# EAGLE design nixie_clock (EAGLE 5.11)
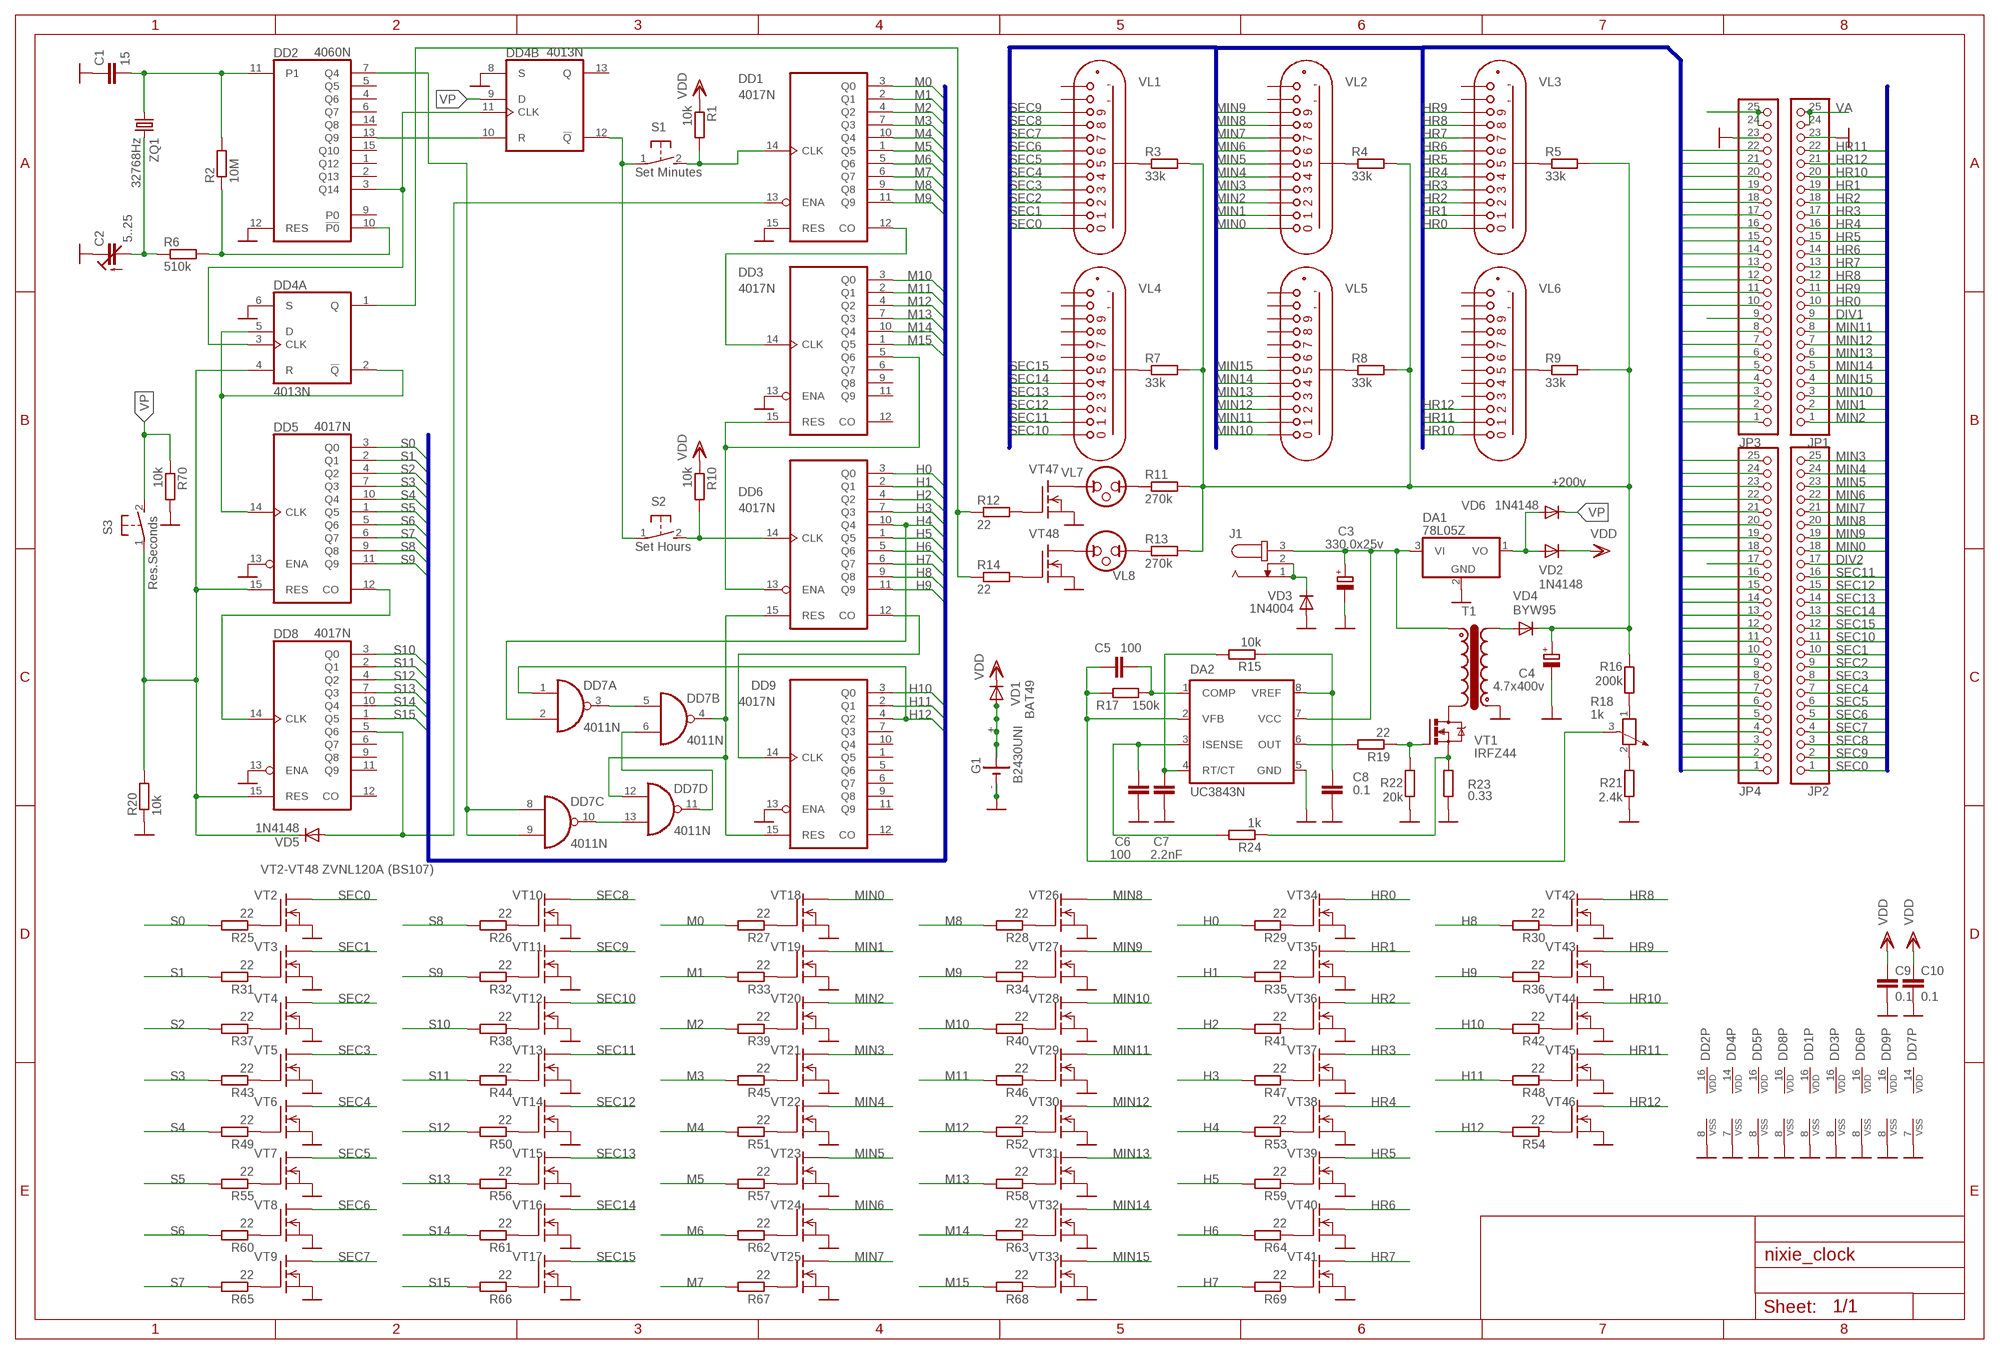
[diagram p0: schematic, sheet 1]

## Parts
C1  15  C-EU050-025X075  [C050-025X075]
C2  5..25  C-TRIMM3040.452  [CTRIM3040.452]
C3  330.0x25v  CPOL-EUE3.5-8  [E3,5-8]
C4  4.7x400v  CPOL-EUE5-10.5  [E5-10,5]
C5  100  C-EU050-025X075  [C050-025X075]
C6  100  C-EU050-025X075  [C050-025X075]
C7  2.2nF  C-EU050-025X075  [C050-025X075]
C8  0.1  C-EU050-025X075  [C050-025X075]
C9  0.1  C-EU050-025X075  [C050-025X075]
C10  0.1  C-EU050-025X075  [C050-025X075]
DA1  78L05Z  78L12Z  [TO92]
DA2  UC3843N  UC3842N  [DIL08]
DD1  4017N  [DIL16]
DD2  4060N  [DIL16]
DD3  4017N  [DIL16]
DD4  4013N  [DIL14]
DD5  4017N  [DIL16]
DD6  4017N  [DIL16]
DD7  4011N  [DIL14]
DD8  4017N  [DIL16]
DD9  4017N  [DIL16]
G1  B2430UNI  [B2430UNI]
J1  JACK-PLUG1  [SPC4078]
JP1  PINHD-1X25  [1X25]
JP2  PINHD-1X25  [1X25]
JP3  PINHD-1X25  [1X25]
JP4  PINHD-1X25  [1X25]
R1  10k  R-EU_0207/12  [0207/12]
R2  10M  R-EU_0207/10  [0207/10]
R3  33k  R-EU_0207/12  [0207/12]
R4  33k  R-EU_0207/12  [0207/12]
R5  33k  R-EU_0207/12  [0207/12]
R6  510k  R-EU_0207/10  [0207/10]
R7  33k  R-EU_0207/12  [0207/12]
R8  33k  R-EU_0207/12  [0207/12]
R9  33k  R-EU_0207/12  [0207/12]
R10  10k  R-EU_0207/12  [0207/12]
R11  270k  R-EU_0207/12  [0207/12]
R12  22  R-EU_0207/10  [0207/10]
R13  270k  R-EU_0207/12  [0207/12]
R14  22  R-EU_0207/2V  [0207/2V]
R15  10k  R-EU_0207/10  [0207/10]
R16  200k  R-EU_0207/10  [0207/10]
R17  150k  R-EU_0207/12  [0207/12]
R18  1k  POTENTIOMETER_PT-10  [PT-10]
R19  22  R-EU_0207/10  [0207/10]
R20  10k  R-EU_0207/12  [0207/12]
R21  2.4k  R-EU_0207/12  [0207/12]
R22  20k  R-EU_0207/12  [0207/12]
R23  0.33  R-EU_0207/10  [0207/10]
R24  1k  R-EU_0207/10  [0207/10]
R25  22  R-EU_0207/2V  [0207/2V]
R26  22  R-EU_0207/2V  [0207/2V]
R27  22  R-EU_0207/10  [0207/10]
R28  22  R-EU_0207/10  [0207/10]
R29  22  R-EU_0207/2V  [0207/2V]
R30  22  R-EU_0207/2V  [0207/2V]
R31  22  R-EU_0207/10  [0207/10]
R32  22  R-EU_0207/10  [0207/10]
R33  22  R-EU_0207/2V  [0207/2V]
R34  22  R-EU_0207/2V  [0207/2V]
R35  22  R-EU_0207/10  [0207/10]
R36  22  R-EU_0207/10  [0207/10]
R37  22  R-EU_0207/2V  [0207/2V]
R38  22  R-EU_0207/2V  [0207/2V]
R39  22  R-EU_0207/10  [0207/10]
R40  22  R-EU_0207/10  [0207/10]
R41  22  R-EU_0207/2V  [0207/2V]
R42  22  R-EU_0207/2V  [0207/2V]
R43  22  R-EU_0207/10  [0207/10]
R44  22  R-EU_0207/10  [0207/10]
R45  22  R-EU_0207/2V  [0207/2V]
R46  22  R-EU_0207/2V  [0207/2V]
R47  22  R-EU_0207/10  [0207/10]
R48  22  R-EU_0207/2V  [0207/2V]
R49  22  R-EU_0207/2V  [0207/2V]
R50  22  R-EU_0207/2V  [0207/2V]
R51  22  R-EU_0207/10  [0207/10]
R52  22  R-EU_0207/10  [0207/10]
R53  22  R-EU_0207/2V  [0207/2V]
R54  22  R-EU_0207/10  [0207/10]
R55  22  R-EU_0207/10  [0207/10]
R56  22  R-EU_0207/10  [0207/10]
R57  22  R-EU_0207/2V  [0207/2V]
R58  22  R-EU_0207/2V  [0207/2V]
R59  22  R-EU_0207/10  [0207/10]
R60  22  R-EU_0207/2V  [0207/2V]
R61  22  R-EU_0207/2V  [0207/2V]
R62  22  R-EU_0207/10  [0207/10]
R63  22  R-EU_0207/10  [0207/10]
R64  22  R-EU_0207/2V  [0207/2V]
R65  22  R-EU_0207/10  [0207/10]
R66  22  R-EU_0207/10  [0207/10]
R67  22  R-EU_0207/2V  [0207/2V]
R68  22  R-EU_0207/2V  [0207/2V]
R69  22  R-EU_0207/10  [0207/10]
R70  10k  R-EU_0207/12  [0207/12]
S1  31-XX  [B3F-31XX]
S2  31-XX  [B3F-31XX]
S3  31-XX  [B3F-31XX]
U$1  TRANSFFB  [EFD20-8]
VD1  BAT49  1N4148DO35-10  [DO35-10]
VD2  1N4148  1N4148DO35-10  [DO35-10]
VD3  1N4004  [DO41-10]
VD4  BYW95  [SOD64-10]
VD5  1N4148  1N4148DO35-10  [DO35-10]
VD6  1N4148  1N4148DO35-10  [DO35-10]
VL1  IN14  [IN14]
VL2  IN14  [IN14]
VL3  IN14  [IN14]
VL4  IN14  [IN14]
VL5  IN14  [IN14]
VL6  IN14  [IN14]
VL7  NE2SMALL  [NE2SMALL]
VL8  NE2SMALL  [NE2SMALL]
VT1  IRFZ44  IRF740  [TO220BV]
VT2  VN2222KM  [TO237]
VT3  VN2222KM  [TO237]
VT4  VN2222KM  [TO237]
VT5  VN2222KM  [TO237]
VT6  VN2222KM  [TO237]
VT7  VN2222KM  [TO237]
VT8  VN2222KM  [TO237]
VT9  VN2222KM  [TO237]
VT10  VN2222KM  [TO237]
VT11  VN2222KM  [TO237]
VT12  VN2222KM  [TO237]
VT13  VN2222KM  [TO237]
VT14  VN2222KM  [TO237]
VT15  VN2222KM  [TO237]
VT16  VN2222KM  [TO237]
VT17  VN2222KM  [TO237]
VT18  VN2222KM  [TO237]
VT19  VN2222KM  [TO237]
VT20  VN2222KM  [TO237]
VT21  VN2222KM  [TO237]
VT22  VN2222KM  [TO237]
VT23  VN2222KM  [TO237]
VT24  VN2222KM  [TO237]
VT25  VN2222KM  [TO237]
VT26  VN2222KM  [TO237]
VT27  VN2222KM  [TO237]
VT28  VN2222KM  [TO237]
VT29  VN2222KM  [TO237]
VT30  VN2222KM  [TO237]
VT31  VN2222KM  [TO237]
VT32  VN2222KM  [TO237]
VT33  VN2222KM  [TO237]
VT34  VN2222KM  [TO237]
VT35  VN2222KM  [TO237]
VT36  VN2222KM  [TO237]
VT37  VN2222KM  [TO237]
VT38  VN2222KM  [TO237]
VT39  VN2222KM  [TO237]
VT40  VN2222KM  [TO237]
VT41  VN2222KM  [TO237]
VT42  VN2222KM  [TO237]
VT43  VN2222KM  [TO237]
VT44  VN2222KM  [TO237]
VT45  VN2222KM  [TO237]
VT46  VN2222KM  [TO237]
VT47  VN2222KM  [TO237]
VT48  VN2222KM  [TO237]
ZQ1  32768Hz  CRYSTALTC38H  [TC38H]

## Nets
DIV: DD4.1(A:Q) R12.1 R14.1
DIV1: JP1.9 JP3.9 VL7.P$1 VT47.1(D)
DIV2: JP2.17 JP4.17 VL8.P$1 VT48.1(D)
GND: C1.1 C2.1A(E) C3.- C4.- C6.1 C7.1 C8.1 C9.1 C10.1 DA1.2(GND) DA2.5(GND) DD1.8(VSS) DD1.15(RES) DD2.8(VSS) DD2.12(RES) DD3.8(VSS) DD3.13(ENA) DD4.6(A:S) DD4.7(P:VSS) DD4.8(B:S) DD5.8(VSS) DD5.13(ENA) DD6.8(VSS) DD7.7(P:VSS) DD8.8(VSS) DD8.13(ENA) DD9.8(VSS) DD9.13(ENA) G1.- G1.-@1(-) JP1.23 JP3.23 R20.1 R21.1 R22.1 R23.1 R70.2 U$1.P$1 VD3.A VT2.3(S) VT3.3(S) VT4.3(S) VT5.3(S) VT6.3(S) VT7.3(S) VT8.3(S) VT9.3(S) VT10.3(S) VT11.3(S) VT12.3(S) VT13.3(S) VT14.3(S) VT15.3(S) VT16.3(S) VT17.3(S) VT18.3(S) VT19.3(S) VT20.3(S) VT21.3(S) VT22.3(S) VT23.3(S) VT24.3(S) VT25.3(S) VT26.3(S) VT27.3(S) VT28.3(S) VT29.3(S) VT30.3(S) VT31.3(S) VT32.3(S) VT33.3(S) VT34.3(S) VT35.3(S) VT36.3(S) VT37.3(S) VT38.3(S) VT39.3(S) VT40.3(S) VT41.3(S) VT42.3(S) VT43.3(S) VT44.3(S) VT45.3(S) VT46.3(S) VT47.3(S) VT48.3(S)
H0: DD6.3(Q0) R29.2
H1: DD6.2(Q1) R35.2
H2: DD6.4(Q2) R41.2
H3: DD6.7(Q3) R47.2
H4: DD6.10(Q4) DD7.2(A:I1) R53.2
H5: DD6.1(Q5) R59.2
H6: DD6.5(Q6) R64.2
H7: DD6.6(Q7) R69.2
H8: DD6.9(Q8) R30.2
H9: DD6.11(Q9) R36.2
H10: DD9.3(Q0) R42.2
H11: DD9.2(Q1) R48.2
H12: DD7.1(A:I0) DD9.4(Q2) R54.2
HR0: JP1.10 JP3.10 VL3.P12 VT34.1(D)
HR1: JP1.19 JP3.19 VL3.P3 VT35.1(D)
HR2: JP1.18 JP3.18 VL3.P4 VT36.1(D)
HR3: JP1.17 JP3.17 VL3.P5 VT37.1(D)
HR4: JP1.16 JP3.16 VL3.P6 VT38.1(D)
HR5: JP1.15 JP3.15 VL3.P7 VT39.1(D)
HR6: JP1.14 JP3.14 VL3.P8 VT40.1(D)
HR7: JP1.13 JP3.13 VL3.P9 VT41.1(D)
HR8: JP1.12 JP3.12 VL3.P10 VT42.1(D)
HR9: JP1.11 JP3.11 VL3.P11 VT43.1(D)
HR10: JP1.20 JP3.20 VL6.P12 VT44.1(D)
HR11: JP1.22 JP3.22 VL6.P3 VT45.1(D)
HR12: JP1.21 JP3.21 VL6.P4 VT46.1(D)
M0: DD1.3(Q0) R27.2
M1: DD1.2(Q1) R33.2
M2: DD1.4(Q2) R39.2
M3: DD1.7(Q3) R45.2
M4: DD1.10(Q4) R51.2
M5: DD1.1(Q5) R57.2
M6: DD1.5(Q6) R62.2
M7: DD1.6(Q7) R67.2
M8: DD1.9(Q8) R28.2
M9: DD1.11(Q9) R34.2
M10: DD3.3(Q0) R40.2
M11: DD3.2(Q1) R46.2
M12: DD3.4(Q2) R52.2
M13: DD3.7(Q3) R58.2
M14: DD3.10(Q4) R63.2
M15: DD3.1(Q5) R68.2
MIN0: JP2.18 JP4.18 VL2.P12 VT18.1(D)
MIN1: JP1.2 JP3.2 VL2.P3 VT19.1(D)
MIN2: JP1.1 JP3.1 VL2.P4 VT20.1(D)
MIN3: JP2.25 JP4.25 VL2.P5 VT21.1(D)
MIN4: JP2.24 JP4.24 VL2.P6 VT22.1(D)
MIN5: JP2.23 JP4.23 VL2.P7 VT23.1(D)
MIN6: JP2.22 JP4.22 VL2.P8 VT24.1(D)
MIN7: JP2.21 JP4.21 VL2.P9 VT25.1(D)
MIN8: JP2.20 JP4.20 VL2.P10 VT26.1(D)
MIN9: JP2.19 JP4.19 VL2.P11 VT27.1(D)
MIN10: JP1.3 JP3.3 VL5.P12 VT28.1(D)
MIN11: JP1.8 JP3.8 VL5.P3 VT29.1(D)
MIN12: JP1.7 JP3.7 VL5.P4 VT30.1(D)
MIN13: JP1.6 JP3.6 VL5.P5 VT31.1(D)
MIN14: JP1.5 JP3.5 VL5.P6 VT32.1(D)
MIN15: JP1.4 JP3.4 VL5.P7 VT33.1(D)
N$1: DD1.12(CO) DD3.14(CLK)
N$2: DD3.5(Q6) DD3.15(RES) DD6.13(ENA)
N$3: DD4.12(B:!Q) S1.1(P) S2.1(P)
N$4: DD6.12(CO) DD9.14(CLK)
N$5: DD6.15(RES) DD7.4(B:O) DD7.12(D:I0) DD9.15(RES)
N$6: R11.1 VL7.P$2
N$7: DD1.14(CLK) R1.2 S1.2(S)
N$8: DD4.2(A:!Q) DD4.5(A:D) DD5.14(CLK)
N$9: DD2.3(Q14) DD4.3(A:CLK) DD4.11(B:CLK)
N$10: DD2.13(Q9) DD4.10(B:R)
N$11: DD1.13(ENA) DD8.5(Q6) VD5.A
N$12: DD5.12(CO) DD8.14(CLK)
N$13: DD7.6(B:I1) DD7.11(D:O)
N$14: DD4.4(A:R) DD5.15(RES) DD8.15(RES) R20.2 S3.1(P) VD5.C
N$15: R27.1 VT18.2(G)
N$16: R33.1 VT19.2(G)
N$17: R39.1 VT20.2(G)
N$18: R45.1 VT21.2(G)
N$19: R51.1 VT22.2(G)
N$20: R57.1 VT23.2(G)
N$21: R62.1 VT24.2(G)
N$22: R67.1 VT25.2(G)
N$23: R68.1 VT33.2(G)
N$24: R63.1 VT32.2(G)
N$25: R58.1 VT31.2(G)
N$26: R52.1 VT30.2(G)
N$27: R46.1 VT29.2(G)
N$28: R40.1 VT28.2(G)
N$29: R34.1 VT27.2(G)
N$30: R28.1 VT26.2(G)
N$31: R29.1 VT34.2(G)
N$32: R35.1 VT35.2(G)
N$33: R41.1 VT36.2(G)
N$34: R47.1 VT37.2(G)
N$35: R53.1 VT38.2(G)
N$36: R59.1 VT39.2(G)
N$37: R64.1 VT40.2(G)
N$38: R69.1 VT41.2(G)
N$39: R54.1 VT46.2(G)
N$40: R48.1 VT45.2(G)
N$41: R42.1 VT44.2(G)
N$42: R36.1 VT43.2(G)
N$43: R30.1 VT42.2(G)
N$44: R25.1 VT2.2(G)
N$45: R31.1 VT3.2(G)
N$46: R37.1 VT4.2(G)
N$47: R43.1 VT5.2(G)
N$48: DA1.1(VO) VD2.A VD6.A
N$49: R19.1 R22.2 VT1.G
N$50: U$1.P$5 VD4.A
N$51: DA2.6(OUT) R19.2
N$52: R23.2 R24.1 VT1.S
N$53: DD6.14(CLK) R10.2 S2.2(S)
N$54: R49.1 VT6.2(G)
N$55: R55.1 VT7.2(G)
N$56: R60.1 VT8.2(G)
N$57: U$1.P$7 VT1.D
N$58: C5.2 DA2.2(VFB) R17.2 R18.3
N$59: R4.1 VL2.P1(ANODE)
N$61: J1.1 J1.2 VD3.C
N$62: R8.1 VL5.P1(ANODE)
N$63: R5.1 VL3.P1(ANODE)
N$64: R9.1 VL6.P1(ANODE)
N$65: R65.1 VT9.2(G)
N$66: R66.1 VT17.2(G)
N$67: R12.2 VT47.2(G)
N$69: R61.1 VT16.2(G)
N$70: R56.1 VT15.2(G)
N$71: R50.1 VT14.2(G)
N$72: R44.1 VT13.2(G)
N$73: R38.1 VT12.2(G)
N$74: R32.1 VT11.2(G)
N$75: R26.1 VT10.2(G)
N$76: R3.1 VL1.P1(ANODE)
N$77: R7.1 VL4.P1(ANODE)
N$78: R14.2 VT48.2(G)
N$80: R13.1 VL8.P$2
N$81: DD7.3(A:O) DD7.5(B:I0)
N$82: R18.2 R21.2
N$83: C8.2 DA2.8(VREF) R15.1
N$84: C7.2 DA2.4(RT/CT) R15.2
N$85: C6.2 DA2.3(ISENSE) R24.2
N$86: R16.1 R18.1
N$87: DD2.10(!P0) R2.1 R6.2
N$88: C1.2 DD2.11(P1) R2.2 ZQ1.1
N$89: C2.2(A) R6.1 ZQ1.2
N$90: C5.1 DA2.1(COMP) R17.1
N$91: DD7.10(C:O) DD7.13(D:I1)
N$92: DD2.7(Q4) DD7.8(C:I0) DD7.9(C:I1)
N$93: G1.+ G1.+@1(+) G1.+@2(+) G1.+@3(+) G1.+@4(+) VD1.A
S0: DD5.3(Q0) R25.2
S1: DD5.2(Q1) R31.2
S2: DD5.4(Q2) R37.2
S3: DD5.7(Q3) R43.2
S4: DD5.10(Q4) R49.2
S5: DD5.1(Q5) R55.2
S6: DD5.5(Q6) R60.2
S7: DD5.6(Q7) R65.2
S8: DD5.9(Q8) R26.2
S9: DD5.11(Q9) R32.2
S10: DD8.3(Q0) R38.2
S11: DD8.2(Q1) R44.2
S12: DD8.4(Q2) R50.2
S13: DD8.7(Q3) R56.2
S14: DD8.10(Q4) R61.2
S15: DD8.1(Q5) R66.2
SEC0: JP2.1 JP4.1 VL1.P12 VT2.1(D)
SEC1: JP2.10 JP4.10 VL1.P3 VT3.1(D)
SEC2: JP2.9 JP4.9 VL1.P4 VT4.1(D)
SEC3: JP2.8 JP4.8 VL1.P5 VT5.1(D)
SEC4: JP2.7 JP4.7 VL1.P6 VT6.1(D)
SEC5: JP2.6 JP4.6 VL1.P7 VT7.1(D)
SEC6: JP2.5 JP4.5 VL1.P8 VT8.1(D)
SEC7: JP2.4 JP4.4 VL1.P9 VT9.1(D)
SEC8: JP2.3 JP4.3 VL1.P10 VT10.1(D)
SEC9: JP2.2 JP4.2 VL1.P11 VT11.1(D)
SEC10: JP2.11 JP4.11 VL4.P12 VT12.1(D)
SEC11: JP2.16 JP4.16 VL4.P3 VT13.1(D)
SEC12: JP2.15 JP4.15 VL4.P4 VT14.1(D)
SEC13: JP2.14 JP4.14 VL4.P5 VT15.1(D)
SEC14: JP2.13 JP4.13 VL4.P6 VT16.1(D)
SEC15: JP2.12 JP4.12 VL4.P7 VT17.1(D)
T1: C3.+ DA1.3(VI) DA2.7(VCC) J1.3 U$1.P$3
VA: C4.+ JP1.24 JP1.25 JP3.24 JP3.25 R3.2 R4.2 R5.2 R7.2 R8.2 R9.2 R11.2 R13.2 R16.2 VD4.C
VDD: C9.2 C10.2 R1.1 R10.1 VD1.C VD2.C
VP: DD4.9(B:D) R70.1 S3.2(S) VD6.C
Unconnected: DD2.1(Q12) DD2.2(Q13) DD2.4(Q6) DD2.5(Q5) DD2.6(Q7) DD2.9(P0) DD2.14(Q8) DD2.15(Q10) DD3.6(Q7) DD3.9(Q8) DD3.11(Q9) DD3.12(CO) DD4.13(B:Q) DD8.6(Q7) DD8.9(Q8) DD8.11(Q9) DD8.12(CO) DD9.1(Q5) DD9.5(Q6) DD9.6(Q7) DD9.7(Q3) DD9.9(Q8) DD9.10(Q4) DD9.11(Q9) DD9.12(CO) VL1.P2(CL) VL1.P13(CR) VL2.P2(CL) VL2.P13(CR) VL3.P2(CL) VL3.P13(CR) VL4.P2(CL) VL4.P8 VL4.P9 VL4.P10 VL4.P11 VL4.P13(CR) VL5.P2(CL) VL5.P8 VL5.P9 VL5.P10 VL5.P11 VL5.P13(CR) VL6.P2(CL) VL6.P5 VL6.P6 VL6.P7 VL6.P8 VL6.P9 VL6.P10 VL6.P11 VL6.P13(CR)

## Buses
S[0..15],M[0..15],H[0..12],DIV
SEC[0..15],MIN[0..15],HR[0..12]

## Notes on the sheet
- VL1 | VL2 | VL3
- Set Minutes
- VL4 | VL5 | VL6
- +200v
- Set Hours
- Res.Seconds
- T1
- VT2-VT48 ZVNL120A (BS107)

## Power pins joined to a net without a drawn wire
VDD: DD1.16(VDD) DD2.16(VDD) DD3.16(VDD) DD4.14(P:VDD) DD5.16(VDD) DD6.16(VDD) DD7.14(P:VDD) DD8.16(VDD) DD9.16(VDD)

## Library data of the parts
C1 C5-C10 = rcl:C-EU: CAPACITOR, European symbol
C2 = rcl:C-TRIMM: Trimm capacitor
C3 C4 = rcl:CPOL-EU: POLARIZED CAPACITOR, European symbol
DA1 = linear:78*: Positive VOLTAGE REGULATOR Source: http://cache.national.com/ds/LM/LM78L05.pdf http://www.fairchildsemi.com/ds/LM/LM7805.pdf
DA2 = v-reg:UC384*: SMPS Controller Source: http://www.fairchildsemi.com/ds/UC/UC3843.pdf
DD1 DD3 DD5 DD6 DD8 DD9 = 40xx:4017: COUNTER/DIVIDER
DD2 = 40xx:4060: 14-stage binary/ripple COUNTER
DD4 = 40xx:4013: Dual D FLIP FLOP, set/reset
DD7 = 40xx:4011: Quad 2-input NAND
G1 = battery:B2430UNI: LI BATTERY
J1 = con-jack:JACK-PLUG: DC POWER JACK Power Jack, DC, Right Angle, Through Hole, Rated 5A at 16VDC, PC Terminals Distributor: Farnell (www.Farnell.de) Drawing: 84N1161.pdf / 84N1162.pdf Manufacturer: SPC Technology (www.spctechnology.com) Type: SPC4077 / SPC 4078
JP1-JP4 = pinhead:PINHD-1X25: PIN HEADER
R1-R17 R19-R70 = rcl:R-EU_: RESISTOR, European symbol
R18 = rcl:POTENTIOMETER_: Potentiometer
S1-S3 = switch-omron:31-XX: OMRON SWITCH
U$1 = rps45:TRANSFFB
VD1 VD2 VD5 VD6 = diode:1N4148: DIODE
VD3 = diode:1N4004: DIODE
VD4 = diode:BYW95: DIODE
VL1-VL6 = rps45:IN14
VL7 VL8 = rps45:NE2
VT1 = transistor-power:IRF740: N-CHANNEL MOS FET
VT2-VT48 = transistor-fet:VN2222KM: N-Channel Enhancement MOSFET (VMOS); 60V; 0,5A; 7,5Ohm
ZQ1 = crystal:CRYSTAL: CRYSTAL

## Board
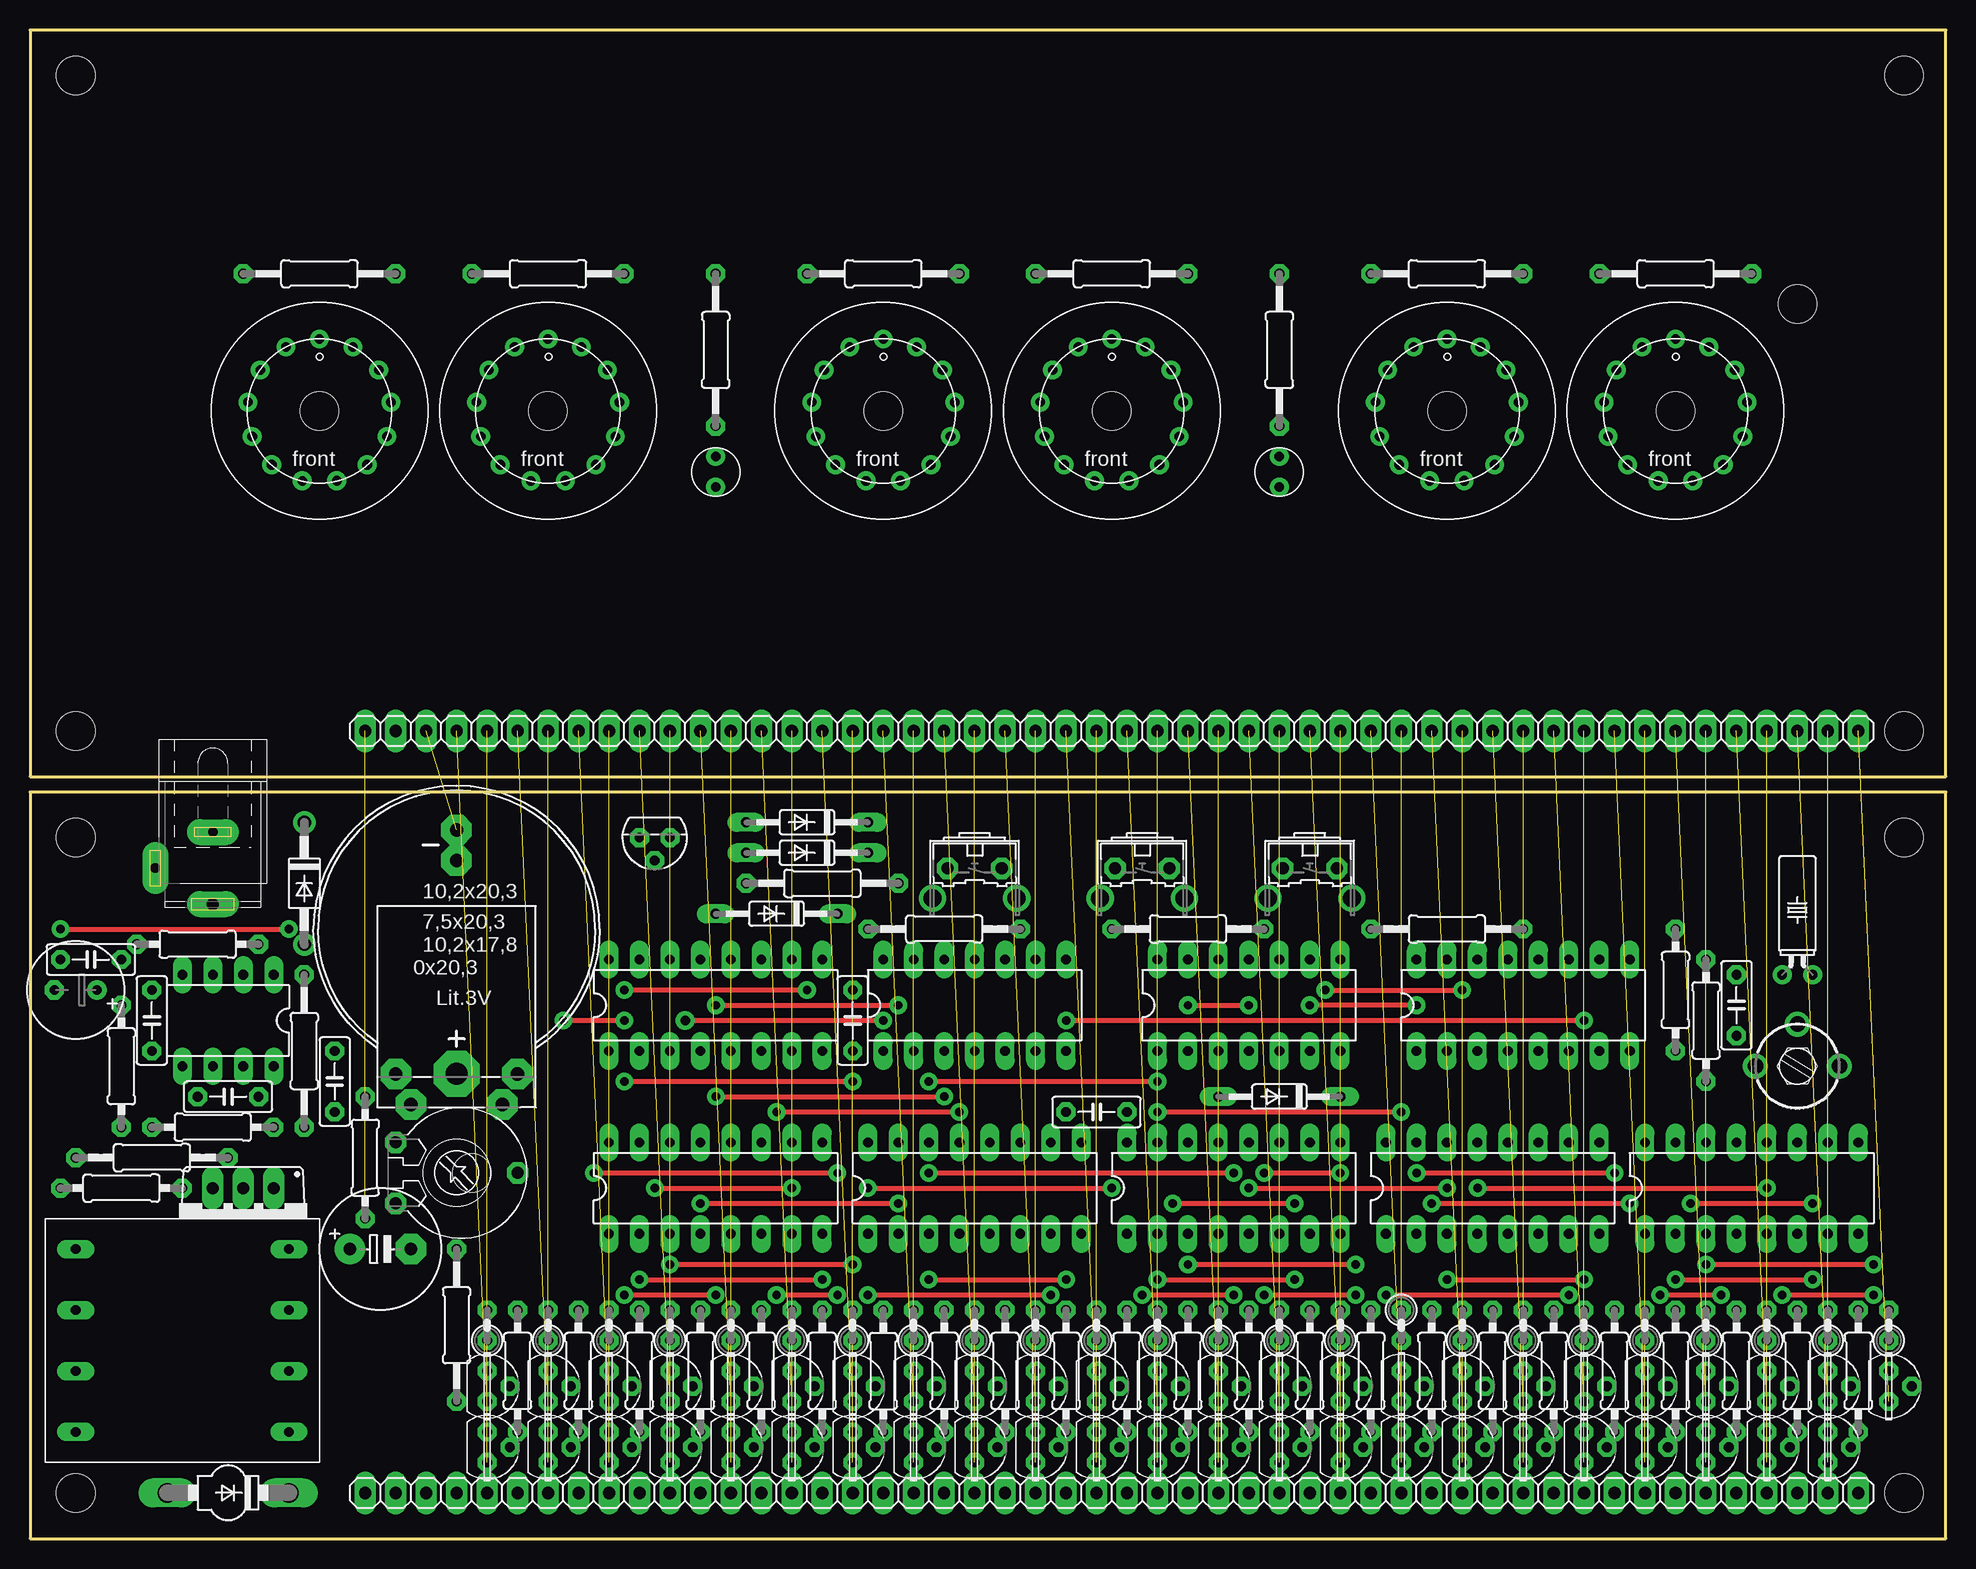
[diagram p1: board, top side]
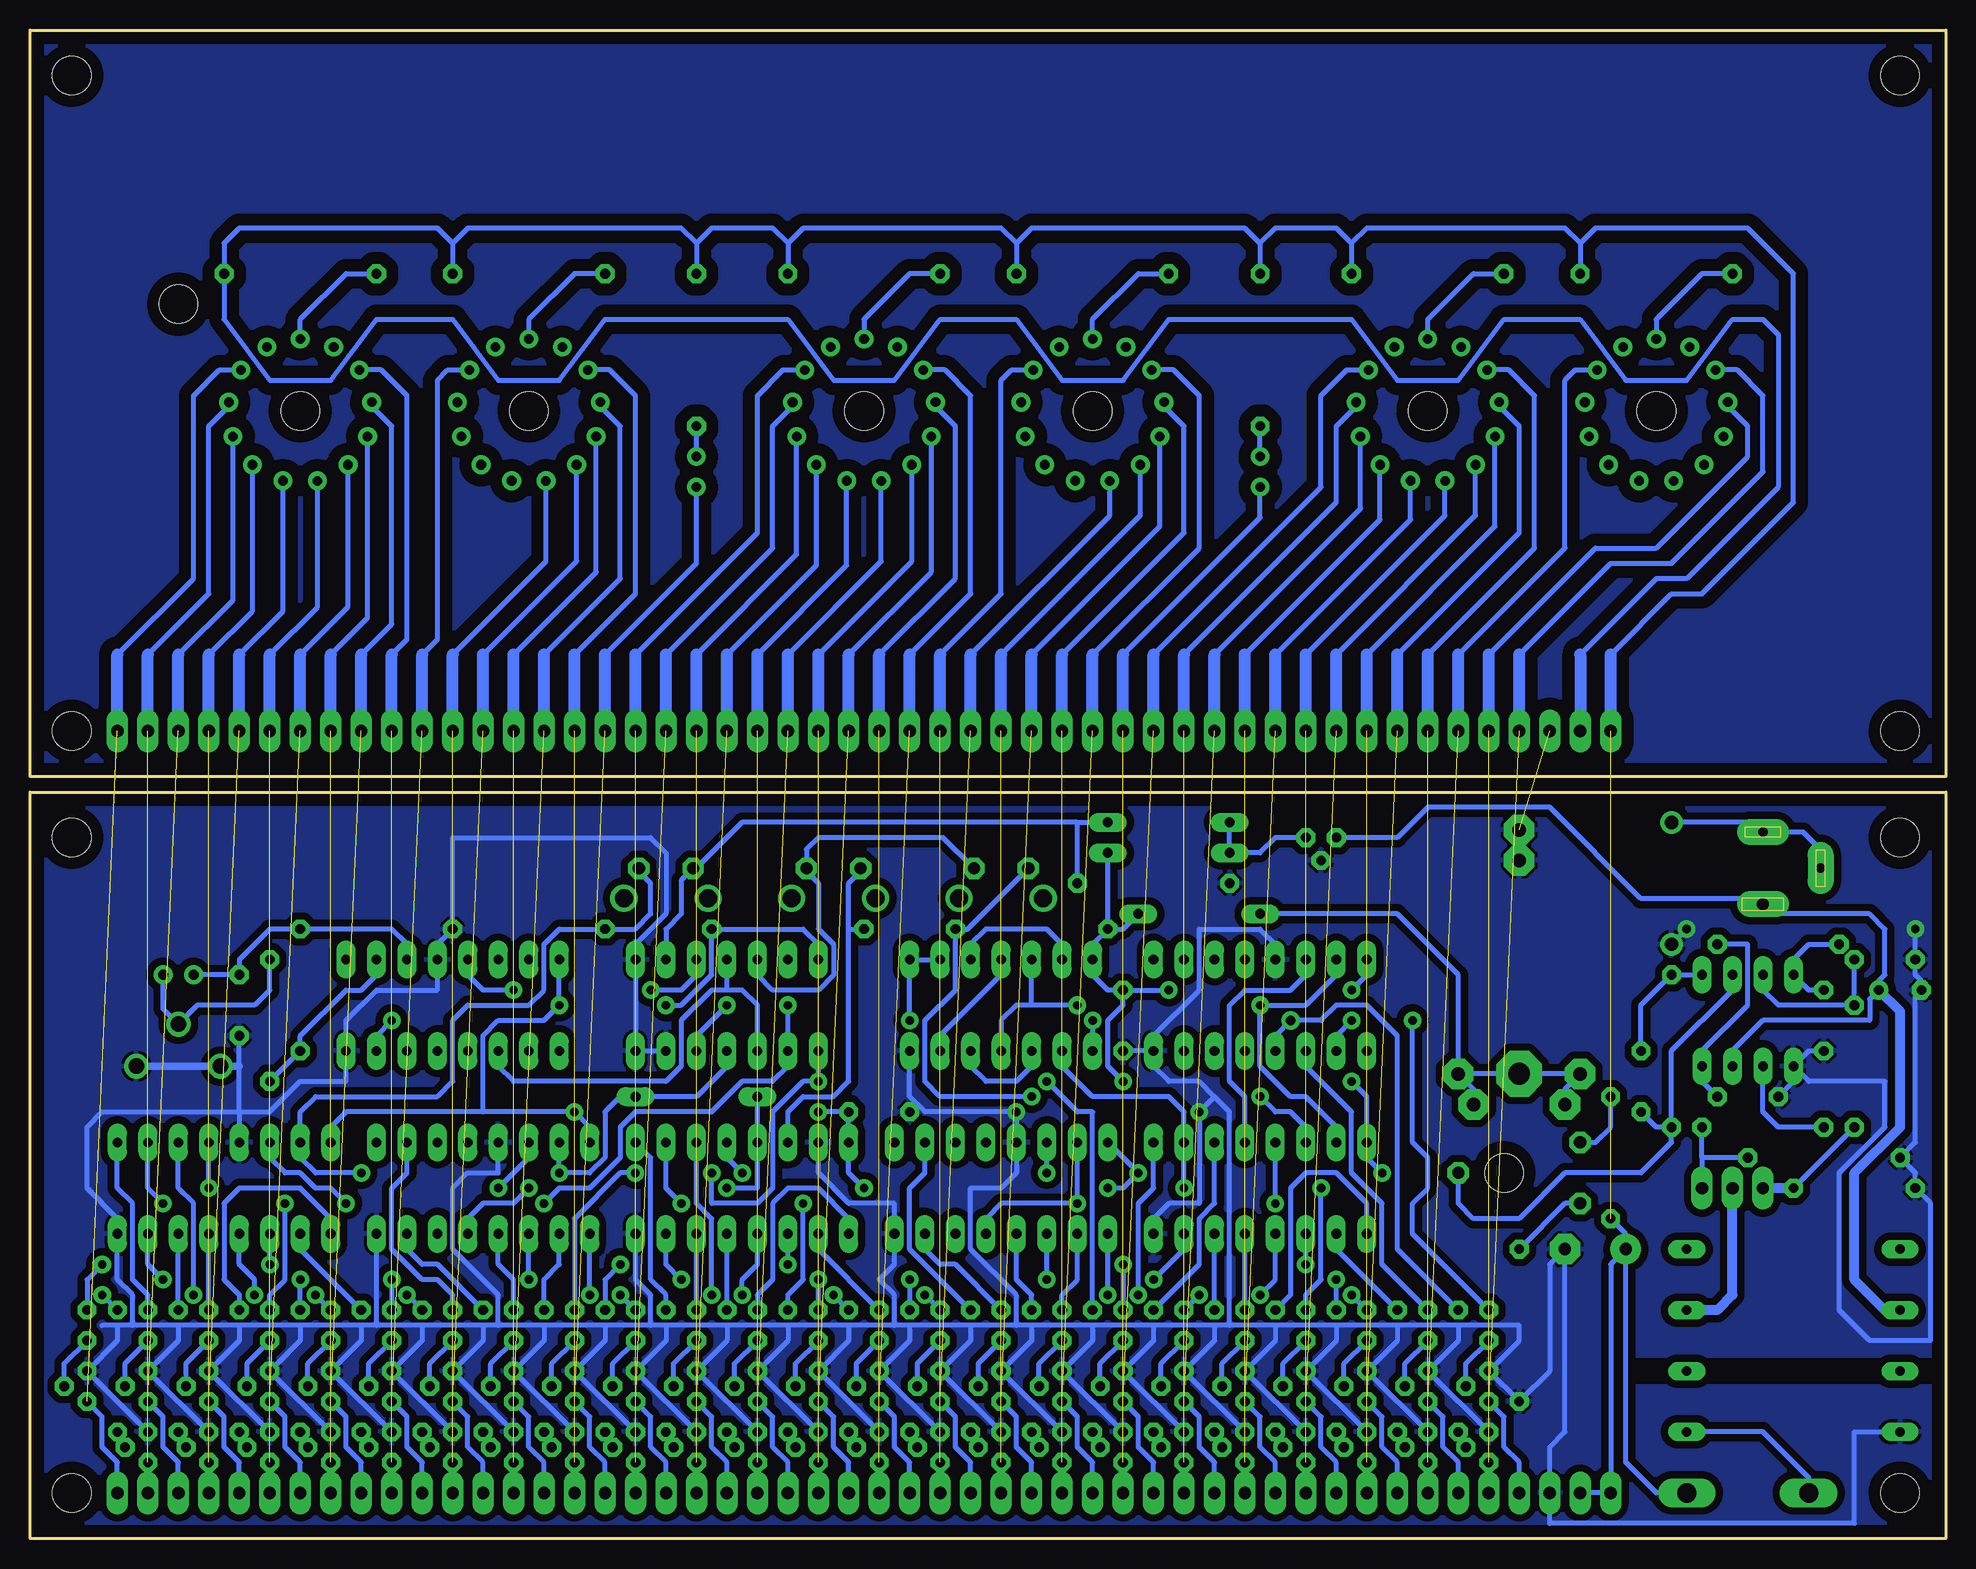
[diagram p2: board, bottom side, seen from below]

Size 159.69 x 125.72 mm. Coordinates in mm from the lower left corner, seen from the top.
Outline: 0,0 159.69,0 159.69,62.22 0,62.22 0,0
Outline: 0,63.5 159.69,63.5 159.69,125.72 0,125.72 0,63.5
Copper layers (1*16): Top 0.035mm / dielectric 1.5mm / Bottom 0.035mm
Design rules "default *": minimum track width 15mil, minimum drill 0.7mm, track to track 8mil, track to pad 8mil, pad to pad 8mil, via to via 8mil, smd to smd 8mil, copper to edge 40mil, drill to drill 8mil, minimum pad ring 15mil, minimum via ring 15mil, stop-mask expansion 4mil, vias tented up to drill 0mil, thermal gap 10mil
Holes 3.2 mm at 3.81,3.81 3.81,58.42 156.21,58.42 156.21,3.81 3.81,67.31 3.81,121.92 156.21,121.92 156.21,67.31 24.13,93.98 43.18,93.98 71.12,93.98 90.17,93.98 118.11,93.98 137.16,93.98 36.83,30.48 147.32,102.87

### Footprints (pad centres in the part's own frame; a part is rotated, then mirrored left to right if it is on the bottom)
C050-025X075 = drill 0.813 octagon: 1 -2.54,0; 2 2.54,0
CTRIM3040.452 = drill 1.3 round: 1A -3.5,0; 1B 3.5,0; 2 0,-3.5
E3,5-8 = drill 0.813 pad 1.6 round: + -1.778,0 | drill 0.813 pad 1.6 octagon: - 1.778,0
E5-10,5 = drill 1.016 pad 2.54 round: + -2.54,0 | drill 1.016 pad 2.54 octagon: - 2.54,0
TO92 = drill 0.813 octagon: 1 -1.27,0; 2 0,1.905; 3 1.27,0
DIL08 = drill 0.813 long: 1 -3.81,-3.81; 2 -1.27,-3.81; 3 1.27,-3.81; 4 3.81,-3.81; 5 3.81,3.81; 6 1.27,3.81; 7 -1.27,3.81; 8 -3.81,3.81
DIL16 = drill 0.813 long: 1 -8.89,-3.81; 2 -6.35,-3.81; 3 -3.81,-3.81; 4 -1.27,-3.81; 5 1.27,-3.81; 6 3.81,-3.81; 7 6.35,-3.81; 8 8.89,-3.81; 9 8.89,3.81; 10 6.35,3.81; 11 3.81,3.81; 12 1.27,3.81; 13 -1.27,3.81; 14 -3.81,3.81; 15 -6.35,3.81; 16 -8.89,3.81
DIL14 = drill 0.813 long: 1 -7.62,-3.81; 2 -5.08,-3.81; 3 -2.54,-3.81; 4 0,-3.81; 5 2.54,-3.81; 6 5.08,-3.81; 7 7.62,-3.81; 8 7.62,3.81; 9 5.08,3.81; 10 2.54,3.81; 11 0,3.81; 12 -2.54,3.81; 13 -5.08,3.81; 14 -7.62,3.81
B2430UNI = drill 1.118 pad 2.54 octagon: + 3.81,14.605; +@1 -3.81,14.605; +@2 -5.08,12.065; +@3 5.08,12.065; - 0,-5.715; -@1 0,-8.255 | drill 1.803 pad 3.81 octagon: +@4 0,12.065
SPC4078 = drill 0.8 pad 2.184 long: 1 -3,0; 2 0,-4.8 | drill 1 pad 2.184 long: 3 3,0
1X25 = drill 1.016 long: 1 -29.21,0; 2 -26.67,0; 3 -24.13,0; 4 -21.59,0; 5 -19.05,0; 6 -16.51,0; 7 -13.97,0; 8 -11.43,0; 9 -8.89,0; 10 -6.35,0; 11 -3.81,0; 12 -1.27,0; 13 1.27,0; 14 3.81,0; 15 6.35,0; 16 8.89,0; 17 11.43,0; 18 13.97,0; 19 16.51,0; 20 19.05,0; 21 21.59,0; 22 24.13,0; 23 26.67,0; 24 29.21,0; 25 31.75,0
0207/12 = drill 0.813 octagon: 1 -6.35,0; 2 6.35,0
0207/10 = drill 0.813 octagon: 1 -5.08,0; 2 5.08,0
0207/2V = drill 0.813 octagon: 1 -1.27,0; 2 1.27,0
PT-10 = drill 1.016 pad 1.778 octagon: 1 -2.54,-5.08; 2 2.54,-5.08; 3 0,5.08
B3F-31XX = drill 1.016 octagon: 1 -2.261,-1.245; 2 2.261,-1.245 | drill 1.499 pad 2.159 round: 3 -3.505,1.245; 4 3.505,1.245
EFD20-8 = drill 0.8 long: P$1 -8.89,-7.62; P$2 -8.89,-2.54; P$3 -8.89,2.54; P$4 -8.89,7.62; P$5 8.89,-7.62; P$6 8.89,-2.54; P$7 8.89,2.54; P$8 8.89,7.62
DO35-10 = drill 0.813 long: A 5.08,0; C -5.08,0
DO41-10 = drill 1.118 round: A 5.08,0; C -5.08,0
SOD64-10 = drill 1.6 long: A 5.08,0; C -5.08,0
IN14 = drill 0.8 round: P1 0,6; P2 -2.786,5.315; P3 -4.935,3.41; P4 -5.958,0.727; P5 -5.61,-2.127; P6 -3.983,-4.49; P7 -1.436,-5.829; P8 1.438,-5.825; P9 3.978,-4.49; P10 5.611,-2.127; P11 5.959,0.719; P12 4.939,3.407; P13 2.783,5.315
NE2SMALL = drill 0.8 pad 1.422 round: P$1 -1.27,0; P$2 1.27,0
TO220BV = drill 1.016 long: D 0,-2.54; G -2.54,-2.54; S 2.54,-2.54
TO237 = drill 0.813 octagon: 1 1.27,0; 2 0,1.905; 3 -1.27,0
TC38H = drill 0.813 round: 1 -1.27,0; 2 1.27,0

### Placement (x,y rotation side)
C1  142.24,44.45 90 top
C2  147.32,39.37 180 top
C3  3.81,45.72 180 top
C4  29.21,24.13 0 top
C5  25.4,38.1 270 top
C6  5.08,48.26 0 top
C7  10.16,43.18 90 top
C8  16.51,36.83 0 top
C9  68.58,43.18 90 top
C10  88.9,35.56 0 top
DA1  52.07,58.42 180 top
DA2  16.51,43.18 180 top
DD1  100.33,29.21 0 top
DD2  124.46,44.45 0 top
DD3  78.74,29.21 0 top
DD4  101.6,44.45 0 top
DD5  143.51,29.21 0 top
DD6  57.15,29.21 0 top
DD7  78.74,44.45 0 top
DD8  121.92,29.21 0 top
DD9  57.15,44.45 0 top
G1  35.56,50.8 180 top
J1  15.24,55.88 270 top
JP1  59.69,3.81 180 top
JP2  123.19,3.81 180 top
JP3  59.69,67.31 180 top
JP4  123.19,67.31 180 top
R1  96.52,50.8 180 top
R2  137.16,45.72 90 top
R3  137.16,105.41 0 top
R4  90.17,105.41 0 top
R5  43.18,105.41 0 top
R6  139.7,43.18 270 top
R7  118.11,105.41 0 top
R8  71.12,105.41 0 top
R9  24.13,105.41 0 top
R10  76.2,50.8 0 top
R11  57.15,99.06 90 top
R12  71.12,13.97 270 top
R13  104.14,99.06 90 top
R14  114.3,17.78 270 top
R15  13.97,49.53 180 top
R16  27.94,31.75 270 top
R17  22.86,40.64 270 top
R18  35.56,30.48 270 top
R19  15.24,34.29 180 top
R20  118.11,50.8 180 top
R21  35.56,17.78 90 top
R22  10.16,31.75 0 top
R23  7.62,29.21 0 top
R24  7.62,39.37 90 top
R25  154.94,17.78 90 top
R26  149.86,17.78 90 top
R27  111.76,13.97 90 top
R28  106.68,13.97 90 top
R29  68.58,17.78 90 top
R30  63.5,17.78 90 top
R31  132.08,13.97 90 top
R32  152.4,13.97 90 top
R33  88.9,17.78 90 top
R34  109.22,17.78 90 top
R35  45.72,13.97 90 top
R36  66.04,13.97 90 top
R37  134.62,17.78 90 top
R38  129.54,17.78 90 top
R39  91.44,13.97 90 top
R40  86.36,13.97 90 top
R41  48.26,17.78 90 top
R42  43.18,17.78 90 top
R43  137.16,13.97 90 top
R44  116.84,13.97 90 top
R45  93.98,17.78 90 top
R46  73.66,17.78 90 top
R47  50.8,13.97 90 top
R48  38.1,17.78 90 top
R49  139.7,17.78 90 top
R50  119.38,17.78 90 top
R51  96.52,13.97 90 top
R52  76.2,13.97 90 top
R53  53.34,17.78 90 top
R54  40.64,13.97 90 top
R55  142.24,13.97 90 top
R56  121.92,13.97 90 top
R57  99.06,17.78 90 top
R58  78.74,17.78 90 top
R59  55.88,13.97 90 top
R60  144.78,17.78 90 top
R61  124.46,17.78 90 top
R62  101.6,13.97 90 top
R63  81.28,13.97 90 top
R64  58.42,17.78 90 top
R65  147.32,13.97 90 top
R66  127,13.97 90 top
R67  104.14,17.78 90 top
R68  83.82,17.78 90 top
R69  60.96,13.97 90 top
R70  66.04,54.61 180 top
S1  92.71,54.61 180 top
S2  78.74,54.61 180 top
S3  106.68,54.61 180 top
U$1  12.7,16.51 0 top
VD1  62.23,52.07 180 top
VD2  64.77,57.15 180 top
VD3  22.86,54.61 270 top
VD4  16.51,3.81 180 top
VD5  104.14,36.83 180 top
VD6  64.77,59.69 180 top
VL1  137.16,93.98 0 top
VL2  90.17,93.98 0 top
VL3  43.18,93.98 0 top
VL4  118.11,93.98 0 top
VL5  71.12,93.98 0 top
VL6  24.13,93.98 0 top
VL7  57.15,88.9 90 top
VL8  104.14,88.9 90 top
VT1  17.78,26.67 180 top
VT2  154.94,12.7 270 top
VT3  129.54,7.62 270 top
VT4  134.62,12.7 270 top
VT5  134.62,7.62 270 top
VT6  139.7,12.7 270 top
VT7  139.7,7.62 270 top
VT8  144.78,12.7 270 top
VT9  144.78,7.62 270 top
VT10  149.86,12.7 270 top
VT11  149.86,7.62 270 top
VT12  129.54,12.7 270 top
VT13  114.3,7.62 270 top
VT14  119.38,12.7 270 top
VT15  119.38,7.62 270 top
VT16  124.46,12.7 270 top
VT17  124.46,7.62 270 top
VT18  109.22,7.62 270 top
VT19  88.9,12.7 270 top
VT20  88.9,7.62 270 top
VT21  93.98,12.7 270 top
VT22  93.98,7.62 270 top
VT23  99.06,12.7 270 top
VT24  99.06,7.62 270 top
VT25  104.14,12.7 270 top
VT26  104.14,7.62 270 top
VT27  109.22,12.7 270 top
VT28  83.82,7.62 270 top
VT29  73.66,12.7 270 top
VT30  73.66,7.62 270 top
VT31  78.74,12.7 270 top
VT32  78.74,7.62 270 top
VT33  83.82,12.7 270 top
VT34  68.58,12.7 270 top
VT35  43.18,7.62 270 top
VT36  48.26,12.7 270 top
VT37  48.26,7.62 270 top
VT38  53.34,12.7 270 top
VT39  53.34,7.62 270 top
VT40  58.42,12.7 270 top
VT41  58.42,7.62 270 top
VT42  63.5,12.7 270 top
VT43  63.5,7.62 270 top
VT44  43.18,12.7 270 top
VT45  38.1,12.7 270 top
VT46  38.1,7.62 270 top
VT47  68.58,7.62 270 top
VT48  114.3,12.7 270 top
ZQ1  147.32,46.99 0 top

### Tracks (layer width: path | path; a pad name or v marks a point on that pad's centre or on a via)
DIV  (via drill 0.7, 0.7 pad 0.81)
  Top 0.406: v74.93,38.1 v93.98,38.1 | v102.87,30.48 v109.22,30.48
  Bottom 0.406: DD4.1 v93.98,38.1 95.25,38.1 97.79,35.56 97.79,29.21 99.06,27.94 102.87,27.94 v102.87,30.48 | R12.1 71.12,35.56 72.39,35.56 v74.93,38.1 | v109.22,30.48 110.49,30.48 114.3,26.67 R14.1
DIV1  (1 unrouted)
  Bottom 0.406: JP1.9 VT47.1 | VL7.P$1 57.15,85.09 68.58,73.66
  Bottom 1.016: JP3.9 68.58,73.66
DIV2  (1 unrouted)
  Bottom 0.406: VT48.1 113.03,10.16 113.03,7.62 111.76,6.35 JP2.17 | 111.76,73.66 104.14,81.28 VL8.P$1
  Bottom 1.016: JP4.17 111.76,73.66
GND  (via drill 0.7)  (1 unrouted)
  Top 0.406: v62.23,35.56 v77.47,35.56 | v2.54,50.8 v21.59,50.8
  Bottom 0.406: VT20.3 VT21.3 91.44,16.51 91.44,17.78 | VT22.3 VT23.3 96.52,16.51 96.52,17.78 | VT24.3 VT25.3 101.6,16.51 101.6,17.78 | VT26.3 VT27.3 106.68,16.51 106.68,17.78 | VT32.3 VT33.3 81.28,16.51 81.28,17.78 | VT30.3 VT31.3 76.2,16.51 76.2,17.78 | VT47.3 VT29.3 71.12,16.51 71.12,17.78 | VT43.3 VT34.3 66.04,16.51 66.04,17.78 | VT41.3 VT42.3 60.96,16.51 60.96,17.78 | VT39.3 VT40.3 55.88,16.51 55.88,17.78 | VT37.3 VT38.3 50.8,16.51 50.8,17.78 | VT35.3 VT36.3 45.72,16.51 45.72,17.78 | 60.96,17.78 66.04,17.78 | 66.04,17.78 71.12,17.78 | 71.12,17.78 76.2,17.78 | 76.2,17.78 77.47,17.78 | 77.47,17.78 81.28,17.78 | 81.28,17.78 86.36,17.78 | 86.36,17.78 87.63,17.78 | 87.63,17.78 91.44,17.78 | 91.44,17.78 96.52,17.78 | 96.52,17.78 101.6,17.78 | 101.6,17.78 106.68,17.78 | 106.68,17.78 107.95,17.78 | VT13.3 VT14.3 116.84,16.51 116.84,17.78 | VT15.3 VT16.3 121.92,16.51 121.92,17.78 | VT17.3 VT12.3 127,16.51 127,17.78 | VT18.3 VT48.3 111.76,16.51 111.76,17.78 | 107.95,17.78 111.76,17.78 | 111.76,17.78 116.84,17.78 | 116.84,17.78 120.65,17.78 | VT3.3 VT4.3 132.08,16.51 132.08,17.78 | VT5.3 VT6.3 137.16,16.51 137.16,17.78 | VT7.3 VT8.3 142.24,16.51 142.24,17.78 | VT9.3 VT10.3 147.32,16.51 147.32,17.78 | 120.65,17.78 121.92,17.78 | 121.92,17.78 127,17.78 | 127,17.78 130.81,17.78 | 130.81,17.78 132.08,17.78 | 132.08,17.78 137.16,17.78 | 137.16,17.78 142.24,17.78 | 142.24,17.78 147.32,17.78 | 147.32,17.78 151.13,17.78 | 151.13,17.78 152.4,17.78 | 152.4,17.78 153.67,17.78 | 151.13,17.78 151.13,20.32 152.4,21.59 DD5.8 152.4,26.67 154.94,29.21 154.94,34.29 153.67,35.56 142.24,35.56 | 130.81,17.78 DD8.8 | DD8.13 120.65,30.48 123.19,30.48 124.46,29.21 124.46,24.13 120.65,20.32 120.65,17.78
  Bottom 0.406: 142.24,35.56 DD5.13 | 142.24,35.56 139.7,35.56 137.16,38.1 133.35,38.1 DD2.8 133.35,43.18 130.81,45.72 125.73,45.72 DD2.12 125.73,49.53 R20.1 124.46,58.42 107.95,58.42 106.68,57.15 106.68,52.07 109.22,49.53 DD4.8 DD4.7 DD4.6 | 87.63,17.78 87.63,20.32 88.9,21.59 87.63,22.86 DD3.8 87.63,27.94 91.44,27.94 93.98,30.48 DD1.15 | DD1.8 109.22,21.59 107.95,20.32 107.95,17.78 | VT11.3 VT2.3 152.4,16.51 152.4,17.78 | VT46.3 VT44.3 40.64,16.51 40.64,17.78 | 142.24,35.56 142.24,39.37 C1.1 | DD7.7 86.36,36.83 85.09,35.56 v77.47,35.56 DD3.13 77.47,30.48 78.74,29.21 81.28,29.21 81.28,24.13 77.47,20.32 77.47,17.78 | DD9.8 66.04,41.91 62.23,45.72 62.23,50.8 57.15,50.8 55.88,49.53 DD9.13 | C8.1 12.7,38.1 DA2.5 | DA2.5 11.43,40.64 C7.1 | DA2.5 11.43,38.1 5.08,38.1 5.08,34.29 8.89,30.48 8.89,19.05 6.35,16.51 1.27,16.51 1.27,27.94 R23.1 2.54,30.48 R22.1 2.54,33.02 2.54,45.21 C3.- 2.03,46.48 2.54,46.99 C6.1 v2.54,50.8 | G1.-@1 G1.- 35.56,55.88 | v21.59,50.8 VD3.A | 60.96,36.83 v62.23,35.56 62.23,27.94 64.77,27.94 66.04,26.67 DD6.8 | U$1.P$1 7.62,8.89 7.62,1.27 33.02,1.27 JP1.23 33.02,7.62 31.75,8.89 C4.- 33.02,22.86 33.02,13.97 R21.1 VT45.3 35.56,16.51 35.56,17.78 40.64,17.78 | VT28.3 VT19.3 86.36,16.51 86.36,17.78 | 40.64,17.78 45.72,17.78 | 45.72,17.78 50.8,17.78 | 50.8,17.78 55.88,17.78 | 55.88,17.78 59.69,17.78 | 59.69,17.78 60.96,17.78 | 59.69,17.78 59.69,35.56 60.96,36.83 | DD9.8 66.04,39.37 64.77,38.1 62.23,38.1 60.96,36.83 | DD9.8 C9.1
  Bottom 0.61: 142.24,39.37 C2.1A
  pour Bottom (isolate 0.61): 0,62.23 0,15.24 26.67,15.24 26.67,12.7 0,12.7 0,0 158.75,0 158.75,62.23
H0  (via drill 0.7)
  Top 0.406: v53.34,22.86 v68.58,22.86
  Bottom 0.406: v68.58,22.86 R29.2 | v53.34,22.86 DD6.3
H1
  Bottom 0.406: DD6.2 50.8,24.13 R35.2
H2  (via drill 0.7)
  Top 0.406: v49.53,20.32 v57.15,20.32
  Bottom 0.406: R41.2 v49.53,20.32 | v57.15,20.32 55.88,21.59 DD6.4
H3  (via drill 0.7)
  Top 0.406: v50.8,21.59 v66.04,21.59
  Bottom 0.406: R47.2 v50.8,21.59 | v66.04,21.59 63.5,24.13 DD6.7
H4  (via drill 0.7)
  Top 0.406: v52.07,29.21 v63.5,29.21
  Bottom 0.406: R53.2 53.34,20.32 52.07,21.59 v52.07,29.21 | v63.5,29.21 DD6.10 63.5,35.56 64.77,36.83 71.12,36.83 73.66,39.37 DD7.2
H5
  Bottom 0.406: R59.2 54.61,20.32 54.61,29.21 53.34,30.48 50.8,30.48 48.26,27.94 DD6.1
H6
  Bottom 0.406: R64.2 DD6.5
H7
  Bottom 0.406: R69.2 DD6.6
H8  (via drill 0.7)
  Top 0.406: v62.23,20.32 v67.31,20.32
  Bottom 0.406: R30.2 v62.23,20.32 | DD6.9 66.04,29.21 67.31,27.94 v67.31,20.32
H9
  Bottom 0.406: R36.2 62.23,22.86 62.23,26.67 60.96,27.94 DD6.11
H10
  Bottom 0.406: R42.2 46.99,22.86 46.99,27.94 49.53,30.48 49.53,35.56 53.34,39.37 DD9.3
H11  (via drill 0.7)
  Top 0.406: v44.45,43.18 v49.53,43.18
  Bottom 0.406: R48.2 44.45,25.4 44.45,27.94 43.18,29.21 43.18,31.75 44.45,33.02 v44.45,43.18 | DD9.2 50.8,41.91 v49.53,43.18
H12  (via drill 0.7, 0.8 pad 0.81)
  Top 0.406: v54.61,43.18 v71.12,43.18
  Bottom 0.406: DD9.4 55.88,41.91 v54.61,43.18 52.07,43.18 50.8,44.45 48.26,44.45 45.72,41.91 45.72,24.13 R54.2 | v71.12,43.18 DD7.1
HR0  (1 unrouted)
  Bottom 0.406: VT34.1 67.31,10.16 67.31,7.62 66.04,6.35 JP1.10 | VL3.P12 49.93,97.39 52.07,95.25 52.07,87.63 66.04,73.66
  Bottom 1.016: JP3.10 66.04,73.66
HR1  (1 unrouted)
  Bottom 0.406: JP1.19 VT35.1 | VL3.P3 36.43,97.39 34.29,95.25 34.29,82.55 43.18,73.66
  Bottom 1.016: JP3.19 43.18,73.66
HR2  (1 unrouted)
  Bottom 0.406: VT36.1 46.99,10.16 46.99,7.62 45.72,6.35 JP1.18 | VL3.P4 37.22,94.37 35.56,92.71 35.56,83.82 45.72,73.66
  Bottom 1.016: JP3.18 45.72,73.66
HR3  (1 unrouted)
  Bottom 0.406: JP1.17 VT37.1 | VL3.P5 37.57,84.35 48.26,73.66
  Bottom 1.016: JP3.17 48.26,73.66
HR4  (1 unrouted)
  Bottom 0.406: VT38.1 52.07,10.16 52.07,7.62 50.8,6.35 JP1.16 | VL3.P6 39.2,85.26 50.8,73.66
  Bottom 1.016: JP3.16 50.8,73.66
HR5  (1 unrouted)
  Bottom 0.406: JP1.15 VT39.1 | VL3.P7 41.74,85.26 53.34,73.66
  Bottom 1.016: JP3.15 53.34,73.66
HR6  (1 unrouted)
  Bottom 0.406: VT40.1 57.15,10.16 57.15,7.62 55.88,6.35 JP1.14 | VL3.P8 44.62,84.92 55.88,73.66
  Bottom 1.016: JP3.14 55.88,73.66
HR7  (1 unrouted)
  Bottom 0.406: JP1.13 VT41.1 | VL3.P9 47.16,84.92 58.42,73.66
  Bottom 1.016: JP3.13 58.42,73.66
HR8  (1 unrouted)
  Bottom 0.406: VT42.1 62.23,10.16 62.23,7.62 60.96,6.35 JP1.12 | VL3.P10 48.79,85.83 60.96,73.66
  Bottom 1.016: JP3.12 60.96,73.66
HR9  (1 unrouted)
  Bottom 0.406: JP1.11 VT43.1 | VL3.P11 49.14,94.37 50.8,92.71 50.8,86.36 63.5,73.66
  Bottom 1.016: JP3.11 63.5,73.66
HR10  (1 unrouted)
  Bottom 0.406: VT44.1 41.91,10.16 41.91,7.62 40.64,6.35 JP1.20 | VL6.P12 30.88,97.39 31.75,96.52 31.75,82.55 40.64,73.66
  Bottom 1.016: JP3.20 40.64,73.66
HR11  (1 unrouted)
  Bottom 0.406: VT45.1 36.83,10.16 36.83,7.62 35.56,6.35 JP1.22 | VL6.P3 17.38,97.39 15.24,95.25 15.24,88.9 22.86,81.28 27.94,81.28 35.56,73.66
  Bottom 1.016: JP3.22 35.56,73.66
HR12  (1 unrouted)
  Bottom 0.406: JP1.21 VT46.1 | VL6.P4 18.17,94.37 16.51,92.71 16.51,90.17 24.13,82.55 29.21,82.55 38.1,73.66
  Bottom 1.016: JP3.21 38.1,73.66
M0  (via drill 0.7)
  Top 0.406: v96.52,22.86 v110.49,22.86
  Bottom 0.406: v96.52,22.86 DD1.3 | v110.49,22.86 111.76,21.59 R27.2
M1
  Bottom 0.406: DD1.2 93.98,24.13 R33.2
M2  (via drill 0.7)
  Top 0.406: v92.71,20.32 v100.33,20.32
  Bottom 0.406: R39.2 v92.71,20.32 | v100.33,20.32 100.33,21.59 99.06,22.86 DD1.4
M3  (via drill 0.7)
  Top 0.406: v93.98,21.59 v105.41,21.59
  Bottom 0.406: R45.2 v93.98,21.59 | v105.41,21.59 106.68,22.86 DD1.7
M4  (via drill 0.7)
  Top 0.406: v95.25,27.94 v105.41,27.94
  Bottom 0.406: R51.2 96.52,20.32 95.25,21.59 v95.25,27.94 | v105.41,27.94 106.68,29.21 DD1.10
M5
  Bottom 0.406: R57.2 99.06,20.32 97.79,21.59 97.79,27.94 96.52,29.21 93.98,29.21 91.44,26.67 DD1.1
M6
  Bottom 0.406: R62.2 DD1.5
M7
  Bottom 0.406: R67.2 DD1.6
M8
  Bottom 0.406: R28.2 106.68,20.32 107.95,21.59 107.95,31.75 DD1.9
M9  (via drill 0.7)
  Top 0.406: v102.87,20.32 v110.49,20.32
  Bottom 0.406: v110.49,20.32 R34.2 | v102.87,20.32 102.87,26.67 104.14,27.94 DD1.11
M10  (via drill 0.7)
  Top 0.406: v74.93,21.59 v86.36,21.59
  Bottom 0.406: v74.93,21.59 DD3.3 | v86.36,21.59 R40.2
M11
  Bottom 0.406: R46.2 73.66,20.32 72.39,21.59 DD3.2
M12
  Bottom 0.406: DD3.4 77.47,21.59 76.2,20.32 R52.2
M13
  Bottom 0.406: DD3.7 85.09,24.13 83.82,22.86 82.55,22.86 R58.2
M14
  Bottom 0.406: R63.2 86.36,24.13 86.36,29.21 85.09,30.48 DD3.10
M15  (via drill 0.7)
  Top 0.406: v69.85,20.32 v85.09,20.32
  Bottom 0.406: v69.85,20.32 DD3.1 | v85.09,20.32 R68.2
MIN0  (1 unrouted)
  Bottom 0.406: JP2.18 VT18.1 | VL2.P12 96.92,97.39 99.06,95.25 99.06,83.82 109.22,73.66
  Bottom 1.016: JP4.18 109.22,73.66
MIN1  (1 unrouted)
  Bottom 0.406: VT19.1 87.63,10.16 87.63,7.62 86.36,6.35 JP1.2 | VL2.P3 83.42,97.39 81.28,95.25 81.28,78.74 86.36,73.66
  Bottom 1.016: JP3.2 86.36,73.66
MIN2  (1 unrouted)
  Bottom 0.406: JP1.1 VT20.1 | VL2.P4 84.21,94.37 82.55,92.71 82.55,80.01 88.9,73.66
  Bottom 1.016: JP3.1 88.9,73.66
MIN3  (1 unrouted)
  Bottom 0.406: VT21.1 92.71,10.16 92.71,7.62 91.44,6.35 JP2.25 | VL2.P5 84.56,80.54 91.44,73.66
  Bottom 1.016: JP4.25 91.44,73.66
MIN4  (1 unrouted)
  Bottom 0.406: JP2.24 VT22.1 | VL2.P6 86.19,81.45 93.98,73.66
  Bottom 1.016: JP4.24 93.98,73.66
MIN5  (1 unrouted)
  Bottom 0.406: VT23.1 97.79,10.16 97.79,7.62 96.52,6.35 JP2.23 | VL2.P7 88.73,81.45 96.52,73.66
  Bottom 1.016: JP4.23 96.52,73.66
MIN6  (1 unrouted)
  Bottom 0.406: JP2.22 VT24.1 | VL2.P8 91.61,81.11 99.06,73.66
  Bottom 1.016: JP4.22 99.06,73.66
MIN7  (1 unrouted)
  Bottom 0.406: VT25.1 102.87,10.16 102.87,7.62 101.6,6.35 JP2.21 | VL2.P9 94.15,81.11 101.6,73.66
  Bottom 1.016: JP4.21 101.6,73.66
MIN8  (1 unrouted)
  Bottom 0.406: JP2.20 VT26.1 | VL2.P10 95.78,82.02 104.14,73.66
  Bottom 1.016: JP4.20 104.14,73.66
MIN9  (1 unrouted)
  Bottom 0.406: VT27.1 107.95,10.16 107.95,7.62 106.68,6.35 JP2.19 | VL2.P11 96.13,94.37 97.79,92.71 97.79,82.55 106.68,73.66
  Bottom 1.016: JP4.19 106.68,73.66
MIN10  (1 unrouted)
  Bottom 0.406: JP1.3 VT28.1 | VL5.P12 77.87,97.39 78.74,96.52 78.74,78.74 83.82,73.66
  Bottom 1.016: JP3.3 83.82,73.66
MIN11  (1 unrouted)
  Bottom 0.406: VT29.1 72.39,10.16 72.39,7.62 71.12,6.35 JP1.8 | VL5.P3 64.37,97.39 62.23,95.25 62.23,82.55 71.12,73.66
  Bottom 1.016: JP3.8 71.12,73.66
MIN12  (1 unrouted)
  Bottom 0.406: JP1.7 VT30.1 | VL5.P4 65.16,94.37 63.5,92.71 63.5,83.82 73.66,73.66
  Bottom 1.016: JP3.7 73.66,73.66
MIN13  (1 unrouted)
  Bottom 0.406: VT31.1 77.47,10.16 77.47,7.62 76.2,6.35 JP1.6 | VL5.P5 65.51,84.35 76.2,73.66
  Bottom 1.016: JP3.6 76.2,73.66
MIN14  (1 unrouted)
  Bottom 0.406: JP1.5 VT32.1 | VL5.P6 67.14,85.26 78.74,73.66
  Bottom 1.016: JP3.5 78.74,73.66
MIN15  (1 unrouted)
  Bottom 0.406: VT33.1 82.55,10.16 82.55,7.62 81.28,6.35 JP1.4 | VL5.P7 69.68,85.26 81.28,73.66
  Bottom 1.016: JP3.4 81.28,73.66
N$1  (via drill 0.7)
  Top 0.406: v74.93,30.48 v100.33,30.48
  Bottom 0.406: v100.33,30.48 101.6,31.75 DD1.12 | v74.93,30.48 DD3.14
N$2  (via drill 0.7)
  Top 0.406: v55.88,27.94 v72.39,27.94
  Bottom 0.406: DD3.5 80.01,26.67 78.74,27.94 v72.39,27.94 DD3.15 | v55.88,27.94 DD6.13
N$3
  Bottom 0.4: S2.1 83.57,58.42 85.09,58.42
  Bottom 0.406: DD4.12 99.06,46.99 97.79,45.72 93.98,45.72 92.71,46.99 92.71,49.53 93.98,50.8 93.98,54.61 94.97,55.6 S1.1 94.97,57.43 93.98,58.42 85.09,58.42
N$4
  Bottom 0.406: DD9.14 53.34,46.99 54.61,45.72 58.42,45.72 59.69,44.45 59.69,38.1 58.42,36.83 DD6.12
N$5  (via drill 0.7)
  Top 0.406: v57.15,44.45 v72.39,44.45
  Bottom 0.406: DD7.4 78.74,43.18 77.47,44.45 76.2,44.45 | 76.2,44.45 DD7.12 | DD9.15 50.8,46.99 53.34,44.45 v57.15,44.45 57.15,39.37 54.61,36.83 53.34,36.83 50.8,34.29 DD6.15 | v72.39,44.45 76.2,44.45
N$6
  Bottom 0.406: VL7.P$2 R11.1
N$7
  Bottom 0.406: S1.2 90.45,55.6 91.44,54.61 91.44,50.8 | 91.44,50.8 91.44,38.1 92.71,36.83 95.25,36.83 96.52,35.56 DD1.14 | 91.44,50.8 R1.2
N$8  (via drill 0.7, 0.7 pad 0.81)
  Top 0.406: v96.52,44.45 v101.6,44.45 | v116.84,27.94 v133.35,27.94
  Bottom 0.406: DD4.5 104.14,41.91 v101.6,44.45 | v96.52,44.45 DD4.2 96.52,39.37 97.79,38.1 100.33,38.1 102.87,35.56 109.22,35.56 110.49,34.29 110.49,31.75 113.03,29.21 115.57,29.21 v116.84,27.94 | DD5.14 139.7,31.75 138.43,30.48 137.16,30.48 135.89,29.21 134.62,29.21 v133.35,27.94
N$9
  Bottom 0.406: DD2.3 120.65,39.37 119.38,38.1 106.68,38.1 105.41,39.37 105.41,43.18 102.87,45.72 101.6,45.72 | DD4.3 99.06,44.45 100.33,45.72 101.6,45.72 | 101.6,45.72 DD4.11
N$10  (via drill 0.7)
  Top 0.406: v107.95,45.72 v119.38,45.72
  Bottom 0.406: DD2.13 123.19,46.99 121.92,45.72 v119.38,45.72 | v107.95,45.72 105.41,45.72 104.14,46.99 DD4.10
N$11  (via drill 0.7)
  Top 0.406: v101.6,29.21 v118.11,29.21
  Bottom 0.406: v101.6,29.21 99.06,29.21 DD1.13 VD5.A | v118.11,29.21 119.38,27.94 121.92,27.94 123.19,26.67 DD8.5
N$12  (via drill 0.7)
  Top 0.406: v120.65,29.21 v144.78,29.21
  Bottom 0.406: v144.78,29.21 DD5.12 | v120.65,29.21 118.11,31.75 DD8.14
N$13
  Bottom 0.406: DD7.11 78.74,46.99 83.82,41.91 DD7.6
N$14  (via drill 0.7)
  Top 0.406: v115.57,30.48 v132.08,30.48
  Bottom 0.4: S3.1 108.94,55.6 107.95,54.61 107.95,52.07 109.22,50.8 R20.2
  Bottom 0.406: v132.08,30.48 135.89,30.48 137.16,31.75 DD5.15 137.16,35.56 135.89,36.83 125.73,36.83 124.46,38.1 124.46,43.18 123.19,44.45 118.11,44.45 116.84,45.72 116.84,49.53 115.57,50.8 R20.2 | DD8.15 v115.57,30.48 113.03,30.48 111.76,31.75 111.76,35.56 110.49,36.83 VD5.C 104.14,36.83 101.6,39.37 DD4.4
N$15
  Bottom 0.406: R27.1 111.76,8.26 VT18.2
N$16
  Bottom 0.406: VT19.2 90.8,14.61 R33.1
N$17
  Bottom 0.406: R39.1 91.44,8.26 VT20.2
N$18
  Bottom 0.406: VT21.2 95.88,14.61 R45.1
N$19
  Bottom 0.406: R51.1 96.52,8.26 VT22.2
N$20
  Bottom 0.406: VT23.2 100.96,14.61 R57.1
N$21
  Bottom 0.406: R62.1 101.6,8.26 VT24.2
N$22
  Bottom 0.406: VT25.2 106.05,14.61 R67.1
N$23
  Bottom 0.406: VT33.2 85.72,14.61 R68.1
N$24
  Bottom 0.406: R63.1 81.28,8.26 VT32.2
N$25
  Bottom 0.406: VT31.2 80.64,14.61 R58.1
N$26
  Bottom 0.406: R52.1 76.2,8.26 VT30.2
N$27
  Bottom 0.406: VT29.2 75.56,14.61 R46.1
N$28
  Bottom 0.406: R40.1 86.36,8.26 VT28.2
N$29
  Bottom 0.406: VT27.2 111.12,14.61 R34.1
N$30
  Bottom 0.406: R28.1 106.68,8.26 VT26.2
N$31
  Bottom 0.406: VT34.2 70.48,14.61 R29.1
N$32
  Bottom 0.406: R35.1 45.72,8.26 VT35.2
N$33
  Bottom 0.406: VT36.2 50.17,14.61 R41.1
N$34
  Bottom 0.406: R47.1 50.8,8.26 VT37.2
N$35
  Bottom 0.406: VT38.2 55.25,14.61 R53.1
N$36
  Bottom 0.406: R59.1 55.88,8.26 VT39.2
N$37
  Bottom 0.406: VT40.2 60.33,14.61 R64.1
N$38
  Bottom 0.406: R69.1 60.96,8.26 VT41.2
N$39
  Bottom 0.406: R54.1 40.64,8.26 VT46.2
N$40
  Bottom 0.406: VT45.2 40.01,14.61 R48.1
N$41
  Bottom 0.406: VT44.2 45.09,14.61 R42.1
N$42
  Bottom 0.406: R36.1 66.04,8.26 VT43.2
N$43
  Bottom 0.406: VT42.2 65.41,14.61 R30.1
N$44
  Bottom 0.406: VT2.2 156.84,14.61 R25.1
N$45
  Bottom 0.406: R31.1 132.08,8.26 VT3.2
N$46
  Bottom 0.406: VT4.2 136.53,14.61 R37.1
N$47
  Bottom 0.406: R43.1 137.16,8.26 VT5.2
N$48
  Bottom 0.4: VD2.A VD6.A
  Bottom 0.406: DA1.1 55.88,58.42 57.15,57.15 VD2.A
N$49
  Bottom 0.406: 20.32,31.75 VT1.G | 20.32,31.75 R19.1 | R22.2 20.32,31.75
N$50
  Bottom 0.406: U$1.P$5 15.24,8.89 11.43,5.08 VD4.A
N$51
  Bottom 0.406: DA2.6 15.24,35.56 13.97,34.29 R19.2
N$52
  Bottom 0.406: R24.1 R23.2
  Bottom 0.813: R23.2 VT1.S
N$53  (via drill 0.7)
  Top 0.406: v57.15,36.83 v76.2,36.83
  Bottom 0.4: S2.2 81.53,50.8 R10.2
  Bottom 0.406: DD6.14 53.34,34.29 54.61,35.56 55.88,35.56 v57.15,36.83 | v76.2,36.83 83.82,36.83 85.09,38.1 85.09,43.18 82.55,45.72 R10.2
N$54
  Bottom 0.406: VT6.2 141.61,14.61 R49.1
N$55
  Bottom 0.406: R55.1 142.24,8.26 VT7.2
N$56
  Bottom 0.406: VT8.2 146.69,14.61 R60.1
N$57
  Bottom 0.813: U$1.P$7 19.05,19.05 17.78,20.32 VT1.D
N$58
  Bottom 0.406: DA2.2 17.78,45.72 22.86,40.64 R17.2 | R17.2 24.13,34.29 C5.2 | R17.2 22.86,33.02 25.4,30.48 31.75,30.48 35.56,26.67 39.37,26.67 40.64,27.94 R18.3
N$59
  Bottom 0.406: R4.1 86.36,105.41 90.17,101.6 VL2.P1
N$61
  Bottom 0.406: VD3.C 16.05,59.69 J1.1 11.89,58.88 10.16,57.15 10.16,56.16 J1.2
N$62
  Bottom 0.406: R8.1 67.31,105.41 71.12,101.6 VL5.P1
N$63
  Bottom 0.406: R5.1 39.37,105.41 43.18,101.6 VL3.P1
N$64
  Bottom 0.406: R9.1 20.32,105.41 24.13,101.6 VL6.P1
N$65
  Bottom 0.406: R65.1 147.32,8.26 VT9.2
N$66
  Bottom 0.406: R66.1 127,8.26 VT17.2
N$67
  Bottom 0.406: R12.2 71.12,8.26 VT47.2
N$69
  Bottom 0.406: VT16.2 126.36,14.61 R61.1
N$70
  Bottom 0.406: R56.1 121.92,8.26 VT15.2
N$71
  Bottom 0.406: VT14.2 121.28,14.61 R50.1
N$72
  Bottom 0.406: R44.1 116.84,8.26 VT13.2
N$73
  Bottom 0.406: VT12.2 131.45,14.61 R38.1
N$74
  Bottom 0.406: R32.1 152.4,8.26 VT11.2
N$75
  Bottom 0.406: VT10.2 151.77,14.61 R26.1
N$76
  Bottom 0.406: R3.1 133.35,105.41 137.16,101.6 VL1.P1
N$77
  Bottom 0.406: R7.1 114.3,105.41 118.11,101.6 VL4.P1
N$78
  Bottom 0.406: VT48.2 116.2,14.61 R14.2
N$80
  Bottom 0.406: VL8.P$2 R13.1
N$81
  Bottom 0.406: DD7.5 81.28,39.37 80.01,38.1 77.47,38.1 76.2,39.37 DD7.3
N$82
  Bottom 0.406: R18.2 31.75,27.94 R21.2
N$83
  Bottom 0.406: R15.1 16.51,49.53 16.51,44.45 20.32,40.64 DA2.8 20.32,38.1 C8.2
N$84
  Bottom 0.406: C7.2 11.43,45.72 DA2.4 12.7,48.26 11.43,49.53 R15.2
N$85
  Bottom 0.406: C6.2 R24.2 13.97,44.45 15.24,45.72 DA2.3
N$86
  Bottom 0.406: R16.1 27.94,34.29 29.21,33.02 R18.1
N$87
  Bottom 0.406: DD2.10 130.81,46.99 132.08,45.72 133.35,45.72 137.16,41.91 R2.1 R6.2
N$88
  Bottom 0.406: DD2.11 128.27,49.53 129.54,50.8 R2.2 139.7,50.8 142.24,48.26 C1.2 ZQ1.1
N$89
  Bottom 0.406: ZQ1.2 148.59,44.14 C2.2 145.74,44.45 140.97,44.45 139.7,45.72 R6.1
N$90
  Bottom 0.406: DA2.1 R17.1 25.4,44.45 C5.1
N$91
  Bottom 0.406: DD7.13 73.66,49.53 74.93,50.8 80.01,50.8 81.28,49.53 DD7.10
N$92  (via drill 0.7)
  Top 0.406: v86.36,43.18 v129.54,43.18
  Bottom 0.406: DD7.9 DD7.8 v86.36,43.18 | DD2.7 130.81,41.91 v129.54,43.18
N$93
  Bottom 0.406: G1.+@2 G1.+@4 G1.+@3 31.75,37.47 G1.+ | G1.+@2 40.64,46.99 45.72,52.07 VD1.A | G1.+@1 39.37,37.47 G1.+@2
N$94
  pour Bottom (isolate 1.016): 0,125.73 0,64.77 160.02,64.77 160.02,125.73
S0  (via drill 0.7)
  Top 0.406: v139.7,22.86 v153.67,22.86
  Bottom 0.406: v139.7,22.86 DD5.3 | v153.67,22.86 154.94,21.59 R25.2
S1
  Bottom 0.406: DD5.2 137.16,24.13 R31.2
S2  (via drill 0.7)
  Top 0.406: v135.89,20.32 v140.97,20.32
  Bottom 0.406: DD5.4 142.24,22.86 140.97,21.59 v140.97,20.32 | R37.2 v135.89,20.32
S3  (via drill 0.7)
  Top 0.406: v137.16,21.59 v148.59,21.59
  Bottom 0.406: R43.2 v137.16,21.59 | v148.59,21.59 149.86,22.86 DD5.7
S4  (via drill 0.7)
  Top 0.406: v138.43,27.94 v148.59,27.94
  Bottom 0.406: R49.2 139.7,20.32 138.43,21.59 v138.43,27.94 | v148.59,27.94 149.86,29.21 DD5.10
S5
  Bottom 0.406: R55.2 142.24,20.32 143.51,21.59 143.51,27.94 142.24,29.21 137.16,29.21 134.62,26.67 DD5.1
S6
  Bottom 0.406: R60.2 DD5.5
S7
  Bottom 0.406: R65.2 DD5.6
S8
  Bottom 0.406: R26.2 149.86,20.32 151.13,21.59 151.13,27.94 152.4,29.21 DD5.9
S9  (via drill 0.7)
  Top 0.406: v146.05,20.32 v153.67,20.32
  Bottom 0.406: DD5.11 147.32,29.21 146.05,27.94 v146.05,20.32 | v153.67,20.32 R32.2
S10  (via drill 0.7)
  Top 0.406: v118.11,21.59 v129.54,21.59
  Bottom 0.406: v118.11,21.59 DD8.3 | v129.54,21.59 R38.2
S11
  Bottom 0.406: R44.2 116.84,21.59 115.57,22.86 DD8.2
S12
  Bottom 0.406: R50.2 119.38,21.59 120.65,22.86 DD8.4
S13
  Bottom 0.406: R56.2 125.73,22.86 127,22.86 128.27,24.13 DD8.7
S14
  Bottom 0.406: R61.2 124.46,20.32 125.73,21.59 127,21.59 129.54,24.13 129.54,29.21 128.27,30.48 DD8.10
S15  (via drill 0.7)
  Top 0.406: v113.03,20.32 v128.27,20.32
  Bottom 0.406: v113.03,20.32 DD8.1 | v128.27,20.32 R66.2
SEC0  (1 unrouted)
  Bottom 0.406: VT2.1 153.67,10.16 153.67,7.62 152.4,6.35 JP2.1 | VL1.P12 143.91,97.39 146.05,95.25 146.05,80.01 152.4,73.66
  Bottom 1.016: JP4.1 152.4,73.66
SEC1  (1 unrouted)
  Bottom 0.406: JP2.10 VT3.1 | VL1.P3 130.41,97.39 128.27,95.25 128.27,74.93 129.54,73.66
  Bottom 1.016: JP4.10 129.54,73.66
SEC2  (1 unrouted)
  Bottom 0.406: VT4.1 133.35,10.16 133.35,7.62 132.08,6.35 JP2.9 | VL1.P4 131.2,94.37 129.54,92.71 129.54,76.2 132.08,73.66
  Bottom 1.016: JP4.9 132.08,73.66
SEC3  (1 unrouted)
  Bottom 0.406: JP2.8 VT5.1 | VL1.P5 131.55,76.73 134.62,73.66
  Bottom 1.016: JP4.8 134.62,73.66
SEC4  (1 unrouted)
  Bottom 0.406: VT6.1 138.43,10.16 138.43,7.62 137.16,6.35 JP2.7 | VL1.P6 133.18,77.64 137.16,73.66
  Bottom 1.016: JP4.7 137.16,73.66
SEC5  (1 unrouted)
  Bottom 0.406: JP2.6 VT7.1 | VL1.P7 135.72,77.64 139.7,73.66
  Bottom 1.016: JP4.6 139.7,73.66
SEC6  (1 unrouted)
  Bottom 0.406: VT8.1 143.51,10.16 143.51,7.62 142.24,6.35 JP2.5 | VL1.P8 138.6,77.3 142.24,73.66
  Bottom 1.016: JP4.5 142.24,73.66
SEC7  (1 unrouted)
  Bottom 0.406: JP2.4 VT9.1 | VL1.P9 141.14,77.3 144.78,73.66
  Bottom 1.016: JP4.4 144.78,73.66
SEC8  (1 unrouted)
  Bottom 0.406: VT10.1 148.59,10.16 148.59,7.62 147.32,6.35 JP2.3 | VL1.P10 142.77,78.21 147.32,73.66
  Bottom 1.016: JP4.3 147.32,73.66
SEC9  (1 unrouted)
  Bottom 0.406: JP2.2 VT11.1 | VL1.P11 143.12,94.37 144.78,92.71 144.78,78.74 149.86,73.66
  Bottom 1.016: JP4.2 149.86,73.66
SEC10  (1 unrouted)
  Bottom 0.406: VT12.1 128.27,10.16 128.27,7.62 127,6.35 JP2.11 | VL4.P12 124.86,97.39 125.73,96.52 125.73,74.93 127,73.66
  Bottom 1.016: JP4.11 127,73.66
SEC11  (1 unrouted)
  Bottom 0.406: JP2.16 VT13.1 | VL4.P3 111.36,97.39 109.22,95.25 109.22,78.74 114.3,73.66
  Bottom 1.016: JP4.16 114.3,73.66
SEC12  (1 unrouted)
  Bottom 0.406: VT14.1 118.11,10.16 118.11,7.62 116.84,6.35 JP2.15 | VL4.P4 112.15,94.37 110.49,92.71 110.49,80.01 116.84,73.66
  Bottom 1.016: JP4.15 116.84,73.66
SEC13  (1 unrouted)
  Bottom 0.406: JP2.14 VT15.1 | VL4.P5 112.5,80.54 119.38,73.66
  Bottom 1.016: JP4.14 119.38,73.66
SEC14  (1 unrouted)
  Bottom 0.406: VT16.1 123.19,10.16 123.19,7.62 121.92,6.35 JP2.13 | VL4.P6 114.13,81.45 121.92,73.66
  Bottom 1.016: JP4.13 121.92,73.66
SEC15  (1 unrouted)
  Bottom 0.406: JP2.12 VT17.1 | VL4.P7 116.67,81.45 124.46,73.66
  Bottom 1.016: JP4.12 124.46,73.66
T1
  Bottom 0.406: DA2.7 17.78,40.64 15.24,43.18 6.35,43.18 6.35,44.96 C3.+ 5.59,46.48 5.08,46.99 5.08,50.8 6.35,52.07 14.43,52.07 J1.3 15.7,53.34 25.4,53.34 33.02,60.96 43.18,60.96 45.72,58.42 DA1.3
  Bottom 0.813: U$1.P$3 5.08,19.05 7.62,21.59 7.62,30.48 3.81,34.29 3.81,43.94 C3.+
VA  (1 unrouted)
  Bottom 0.406: VD4.C 24.13,3.81 26.67,6.35 C4.+ | C4.+ 26.67,25.4 R16.2 | C4.+ 27.94,22.86 JP1.25 JP1.24 | 124.46,107.95 125.73,109.22 142.24,109.22 143.51,107.95 R3.2 143.51,101.6 139.7,96.52 134.62,96.52 130.81,101.6 124.46,101.6 120.65,96.52 115.57,96.52 111.76,101.6 96.52,101.6 92.71,96.52 87.63,96.52 83.82,101.6 77.47,101.6 73.66,96.52 68.58,96.52 64.77,101.6 49.53,101.6 45.72,96.52 40.64,96.52 36.83,101.6 30.48,101.6 26.67,96.52 21.59,96.52 17.78,101.6 15.24,101.6 13.97,100.33 13.97,87.63 21.59,80.01 24.13,80.01 30.48,73.66 | 124.46,107.95 123.19,109.22 105.41,109.22 104.14,107.95 | 104.14,107.95 102.87,109.22 97.79,109.22 96.52,107.95 | 96.52,107.95 95.25,109.22 78.74,109.22 77.47,107.95 | 77.47,107.95 76.2,109.22 58.42,109.22 57.15,107.95 | 57.15,107.95 55.88,109.22 50.8,109.22 49.53,107.95 | 49.53,107.95 48.26,109.22 31.75,109.22 30.48,107.95 | 30.48,107.95 29.21,109.22 16.51,109.22 12.7,105.41 12.7,86.36 20.32,78.74 22.86,78.74 27.94,73.66 | 49.53,107.95 R5.2 | 57.15,107.95 R11.2 | 96.52,107.95 R4.2 | 30.48,107.95 R9.2 | 77.47,107.95 R8.2 | 124.46,107.95 R7.2 | 104.14,107.95 R13.2
  Bottom 1.016: JP3.25 27.94,73.66 | 30.48,73.66 JP3.24
VDD  (via drill 0.7)
  Top 0.406: v115.57,44.45 v106.68,44.45 | v46.99,30.48 v67.31,30.48 | v69.85,29.21 v90.17,29.21 | v64.77,45.72 v49.53,45.72 | v49.53,38.1 v68.58,38.1 | v93.98,35.56 v114.3,35.56
  Bottom 0.4: v106.68,44.45 105.41,44.45 102.87,46.99 R1.1 | VD1.C 68.58,50.8 R10.1
  Bottom 0.406: DD5.16 134.62,34.29 133.35,35.56 121.92,35.56 | 121.92,35.56 v114.3,35.56 113.03,34.29 DD8.16 | DD4.14 93.98,49.53 95.25,50.8 R1.1 | DD2.16 v115.57,44.45 116.84,43.18 120.65,43.18 121.92,41.91 121.92,35.56 | v46.99,30.48 48.26,31.75 DD6.16 48.26,36.83 v49.53,38.1 | DD3.16 v67.31,30.48 68.58,29.21 v69.85,29.21 | v90.17,29.21 91.44,30.48 DD1.16 C10.2 v93.98,35.56 | v49.53,45.72 48.26,46.99 DD9.16 | v68.58,38.1 69.85,39.37 69.85,43.18 68.58,44.45 C9.2 | VD2.C R10.1 71.12,49.53 DD7.14 71.12,46.99 69.85,45.72 C9.2 | C9.2 v64.77,45.72
VP
  Bottom 0.4: 72.39,59.69 100.33,59.69 104.16,55.86 S3.2 105.41,54.86 105.41,52.07 106.68,50.8 DD4.9 | R70.1 72.39,59.69 | 72.39,59.69 VD6.C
